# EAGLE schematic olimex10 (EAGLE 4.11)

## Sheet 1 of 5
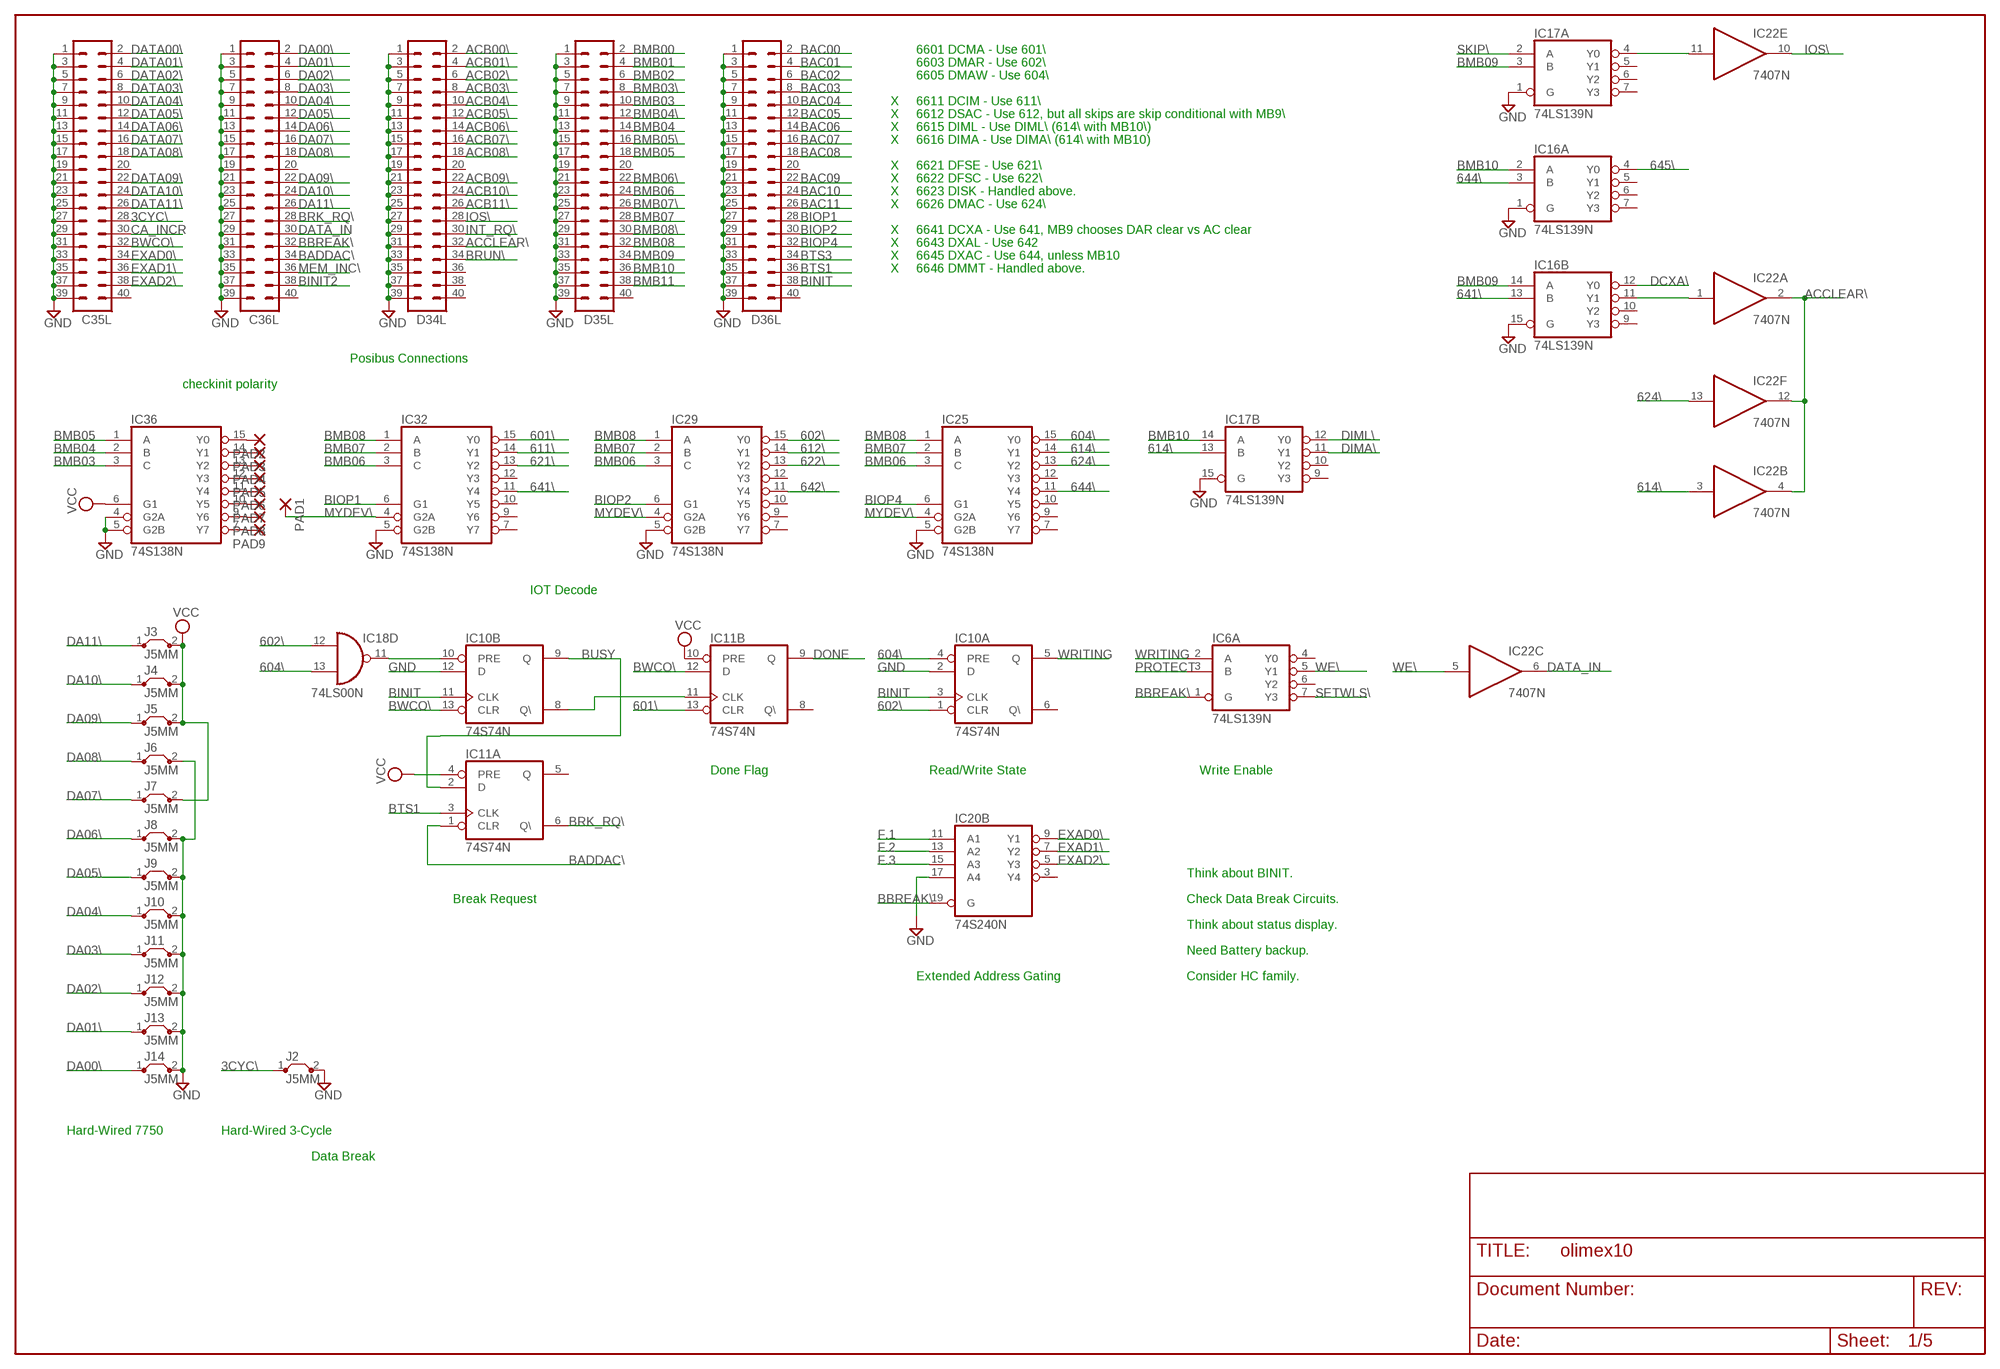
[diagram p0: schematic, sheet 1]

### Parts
C35L  MA20-2  [MA20-2]
C36L  MA20-2  [MA20-2]
D34L  MA20-2  [MA20-2]
D35L  MA20-2  [MA20-2]
D36L  MA20-2  [MA20-2]
IC6  74LS139N  74S139N  [DIL16]
IC10  74S74N  [DIL14]
IC11  74S74N  [DIL14]
IC16  74LS139N  74S139N  [DIL16]
IC17  74LS139N  74S139N  [DIL16]
IC18  74LS00N  [DIL14]
IC20  74S240N  [DIL20]
IC22  7407N  [DIL14]
IC25  74S138N  [DIL16]
IC29  74S138N  [DIL16]
IC32  74S138N  [DIL16]
IC36  74S138N  [DIL16]
J2  J5MM  [05]
J3  J5MM  [05]
J4  J5MM  [05]
J5  J5MM  [05]
J6  J5MM  [05]
J7  J5MM  [05]
J8  J5MM  [05]
J9  J5MM  [05]
J10  J5MM  [05]
J11  J5MM  [05]
J12  J5MM  [05]
J13  J5MM  [05]
J14  J5MM  [05]
PAD1  1,6/0,8  [1,6/0,8]
PAD2  1,6/0,8  [1,6/0,8]
PAD3  1,6/0,8  [1,6/0,8]
PAD4  1,6/0,8  [1,6/0,8]
PAD5  1,6/0,8  [1,6/0,8]
PAD6  1,6/0,8  [1,6/0,8]
PAD7  1,6/0,8  [1,6/0,8]
PAD8  1,6/0,8  [1,6/0,8]
PAD9  1,6/0,8  [1,6/0,8]

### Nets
3CYC\: C35L.28 J2.1
601\: IC11.13(B:CLR) IC32.15(Y0) ; also sheet 2
602\: IC10.1(A:CLR) IC18.12(D:I0) IC29.15(Y0) ; also sheet 2
604\: IC10.4(A:PRE) IC18.13(D:I1) IC25.15(Y0) ; also sheet 2
611\: IC32.14(Y1) ; also sheet 2
612\: IC29.14(Y1) ; also sheet 2
614\: IC17.13(B:B) IC22.3(B:I) IC25.14(Y1)
621\: IC32.13(Y2) ; also sheet 2
622\: IC29.13(Y2) ; also sheet 2
624\: IC22.13(F:I) IC25.13(Y2) ; also sheet 2
641\: IC16.13(B:B) IC32.11(Y4)
642\: IC29.11(Y4) ; also sheet 2
644\: IC16.3(A:B) IC25.11(Y4)
645\: IC16.4(A:Y0) ; also sheet 2
ACB00\: D34L.2 ; also sheet 2
ACB01\: D34L.4 ; also sheet 2
ACB02\: D34L.6 ; also sheet 2
ACB03\: D34L.8 ; also sheet 2
ACB04\: D34L.10 ; also sheet 2
ACB05\: D34L.12 ; also sheet 2
ACB06\: D34L.14 ; also sheet 2
ACB07\: D34L.16 ; also sheet 2
ACB08\: D34L.18 ; also sheet 2
ACB09\: D34L.22 ; also sheet 2
ACB10\: D34L.24 ; also sheet 2
ACB11\: D34L.26 ; also sheet 2
ACCLEAR\: D34L.32 IC22.2(A:O) IC22.4(B:O) IC22.12(F:O)
BAC00: D36L.2 ; also sheet 2
BAC01: D36L.4 ; also sheet 2
BAC02: D36L.6 ; also sheet 2
BAC03: D36L.8 ; also sheet 2
BAC04: D36L.10 ; also sheet 2
BAC05: D36L.12 ; also sheet 2
BAC06: D36L.14 ; also sheet 2
BAC07: D36L.16 ; also sheet 2
BAC08: D36L.18 ; also sheet 2
BAC09: D36L.22 ; also sheet 2
BAC10: D36L.24 ; also sheet 2
BAC11: D36L.26 ; also sheet 2
BADDAC\: C36L.34 IC11.1(A:CLR)
BBREAK\: C36L.32 IC6.1(A:G) IC20.19(B:G) ; also sheet 2,3
BINIT: D36L.38 IC10.3(A:CLK) IC10.11(B:CLK) ; also sheet 2
BINIT2: C36L.38
BIOP1: D36L.28 IC32.6(G1)
BIOP2: D36L.30 IC29.6(G1)
BIOP4: D36L.32 IC25.6(G1)
BMB00: D35L.2 ; also sheet 3
BMB01: D35L.4 ; also sheet 3
BMB02: D35L.6 ; also sheet 3
BMB03: D35L.10 IC36.3(C) ; also sheet 3
BMB03\: D35L.8
BMB04: D35L.14 IC36.2(B) ; also sheet 3
BMB04\: D35L.12
BMB05: D35L.18 IC36.1(A) ; also sheet 3
BMB05\: D35L.16
BMB06: D35L.24 IC25.3(C) IC29.3(C) IC32.3(C) ; also sheet 3
BMB06\: D35L.22
BMB07: D35L.28 IC25.2(B) IC29.2(B) IC32.2(B) ; also sheet 3
BMB07\: D35L.26
BMB08: D35L.32 IC25.1(A) IC29.1(A) IC32.1(A) ; also sheet 3
BMB08\: D35L.30
BMB09: D35L.34 IC16.14(B:A) IC17.3(A:B) ; also sheet 3
BMB10: D35L.36 IC16.2(A:A) IC17.14(B:A) ; also sheet 3
BMB11: D35L.38 ; also sheet 3
BRK_RQ\: C36L.28 IC11.6(A:Q\) ; also sheet 4,5
BRUN\: D34L.34
BTS1: D36L.36 IC11.3(A:CLK)
BTS3: D36L.34
BUSY: IC10.9(B:Q) IC11.2(A:D) ; also sheet 2
BWCO\: C35L.32 IC10.13(B:CLR) IC11.12(B:D) ; also sheet 4,5
CA_INCR: C35L.30
DA00\: C36L.2 J14.1
DA01\: C36L.4 J13.1
DA02\: C36L.6 J12.1
DA03\: C36L.8 J11.1
DA04\: C36L.10 J10.1
DA05\: C36L.12 J9.1
DA06\: C36L.14 J8.1
DA07\: C36L.16 J7.1
DA08\: C36L.18 J6.1
DA09\: C36L.22 J5.1
DA10\: C36L.24 J4.1
DA11\: C36L.26 J3.1
DATA00\: C35L.2 ; also sheet 3
DATA01\: C35L.4 ; also sheet 3
DATA02\: C35L.6 ; also sheet 3
DATA03\: C35L.8 ; also sheet 3
DATA04\: C35L.10 ; also sheet 3
DATA05\: C35L.12 ; also sheet 3
DATA06\: C35L.14 ; also sheet 3
DATA07\: C35L.16 ; also sheet 3
DATA08\: C35L.18 ; also sheet 3
DATA09\: C35L.22 ; also sheet 3
DATA10\: C35L.24 ; also sheet 3
DATA11\: C35L.26 ; also sheet 3
DATA_IN: C36L.30 IC22.6(C:O)
DCXA\: IC16.12(B:Y0) ; also sheet 2
DIMA\: IC17.11(B:Y1) ; also sheet 2
DIML\: IC17.12(B:Y0) ; also sheet 2
DONE: IC11.9(B:Q) ; also sheet 2,4,5
EXAD0\: C35L.34 IC20.9(B:Y1)
EXAD1\: C35L.36 IC20.7(B:Y2)
EXAD2\: C35L.38 IC20.5(B:Y3)
F.1: IC20.11(B:A1) ; also sheet 2,4,5
F.2: IC20.13(B:A2) ; also sheet 2,4,5
F.3: IC20.15(B:A3) ; also sheet 2,4,5
GND: C35L.1 C35L.3 C35L.5 C35L.7 C35L.9 C35L.11 C35L.13 C35L.15 C35L.17 C35L.19 C35L.21 C35L.23 C35L.25 C35L.27 C35L.29 C35L.31 C35L.33 C35L.35 C35L.37 C35L.39 C36L.1 C36L.3 C36L.5 C36L.7 C36L.9 C36L.11 C36L.13 C36L.15 C36L.17 C36L.19 C36L.21 C36L.23 C36L.25 C36L.27 C36L.29 C36L.31 C36L.33 C36L.35 C36L.37 C36L.39 D34L.1 D34L.3 D34L.5 D34L.7 D34L.9 D34L.11 D34L.13 D34L.15 D34L.17 D34L.19 D34L.21 D34L.23 D34L.25 D34L.27 D34L.29 D34L.31 D34L.33 D34L.35 D34L.37 D34L.39 D35L.1 D35L.3 D35L.5 D35L.7 D35L.9 D35L.11 D35L.13 D35L.15 D35L.17 D35L.19 D35L.21 D35L.23 D35L.25 D35L.27 D35L.29 D35L.31 D35L.33 D35L.35 D35L.37 D35L.39 D36L.1 D36L.3 D36L.5 D36L.7 D36L.9 D36L.11 D36L.13 D36L.15 D36L.17 D36L.19 D36L.21 D36L.23 D36L.25 D36L.27 D36L.29 D36L.31 D36L.33 D36L.35 D36L.37 D36L.39 IC10.2(A:D) IC10.12(B:D) IC16.1(A:G) IC16.15(B:G) IC17.1(A:G) IC17.15(B:G) IC20.17(B:A4) IC25.5(G2B) IC29.5(G2B) IC32.5(G2B) IC36.4(G2A) IC36.5(G2B) J2.2 J6.2 J8.2 J9.2 J10.2 J11.2 J12.2 J13.2 J14.2 ; also sheet 2,3,4,5
INT_RQ\: D34L.30 ; also sheet 2
IOS\: D34L.28 IC22.10(E:O)
MEM_INC\: C36L.36
MYDEV\: IC25.4(G2A) IC29.4(G2A) IC32.4(G2A) PAD1.1(P)
N$1: IC36.9(Y6) PAD8.1(P)
N$2: IC10.8(B:Q\) IC11.11(B:CLK)
N$5: IC36.15(Y0) PAD2.1(P)
N$6: IC36.14(Y1) PAD3.1(P)
N$7: IC36.13(Y2) PAD4.1(P)
N$8: IC36.12(Y3) PAD5.1(P)
N$9: IC36.11(Y4) PAD6.1(P)
N$10: IC36.10(Y5) PAD7.1(P)
N$11: IC36.7(Y7) PAD9.1(P)
N$26: IC16.11(B:Y1) IC22.1(A:I)
N$27: IC17.4(A:Y0) IC22.11(E:I)
N$31: IC10.10(B:PRE) IC18.11(D:O)
PROTECT: IC6.3(A:B) ; also sheet 3
SETWLS\: IC6.7(A:Y3) ; also sheet 2
SKIP\: IC17.2(A:A) ; also sheet 2
VCC [Power]: IC11.4(A:PRE) IC11.10(B:PRE) IC36.6(G1) J3.2 J4.2 J5.2 J7.2 ; also sheet 2,3,4,5
WE\: IC6.5(A:Y1) IC22.5(C:I) ; also sheet 3,4
WRITING: IC6.2(A:A) IC10.5(A:Q) ; also sheet 3,4,5
Unconnected: C35L.20 C35L.40 C36L.20 C36L.40 D34L.20 D34L.36 D34L.38 D34L.40 D35L.20 D35L.40 D36L.20 D36L.40 IC6.4(A:Y0) IC6.6(A:Y2) IC6.9(B:Y3) IC6.10(B:Y2) IC6.11(B:Y1) IC6.12(B:Y0) IC6.13(B:B) IC6.14(B:A) IC6.15(B:G) IC10.6(A:Q\) IC11.5(A:Q) IC11.8(B:Q\) IC16.5(A:Y1) IC16.6(A:Y2) IC16.7(A:Y3) IC16.9(B:Y3) IC16.10(B:Y2) IC17.5(A:Y1) IC17.6(A:Y2) IC17.7(A:Y3) IC17.9(B:Y3) IC17.10(B:Y2) IC20.1(A:G) IC20.2(A:A1) IC20.3(B:Y4) IC20.4(A:A2) IC20.6(A:A3) IC20.8(A:A4) IC20.12(A:Y4) IC20.14(A:Y3) IC20.16(A:Y2) IC20.18(A:Y1) IC22.8(D:O) IC22.9(D:I) IC25.7(Y7) IC25.9(Y6) IC25.10(Y5) IC25.12(Y3) IC29.7(Y7) IC29.9(Y6) IC29.10(Y5) IC29.12(Y3) IC32.7(Y7) IC32.9(Y6) IC32.10(Y5) IC32.12(Y3)

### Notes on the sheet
- 6601 DCMA - Use 601\
- 6603 DMAR - Use 602\
- 6605 DMAW - Use 604\
- X | 6611 DCIM - Use 611\
- X | 6612 DSAC - Use 612\, but all skips are skip conditional with MB9\
- X | 6615 DIML - Use DIML\ (614\ with MB10\)
- X | 6616 DIMA - Use DIMA\ (614\ with MB10)
- X | 6621 DFSE - Use 621\
- X | 6622 DFSC - Use 622\
- X | 6623 DISK - Handled above.
- X | 6626 DMAC - Use 624\
- X | 6641 DCXA - Use 641, MB9 chooses DAR clear vs AC clear
- X | 6643 DXAL - Use 642
- X | 6645 DXAC - Use 644, unless MB10
- X | 6646 DMMT - Handled above.
- Posibus Connections
- checkinit polarity
- IOT Decode
- Done Flag | Read/Write State | Write Enable
- Think about BINIT.
- Break Request | Check Data Break Circuits.
- Think about status display.
- Need Battery backup.
- Extended Address Gating | Consider HC family.
- Hard-Wired 7750 | Hard-Wired 3-Cycle
- Data Break

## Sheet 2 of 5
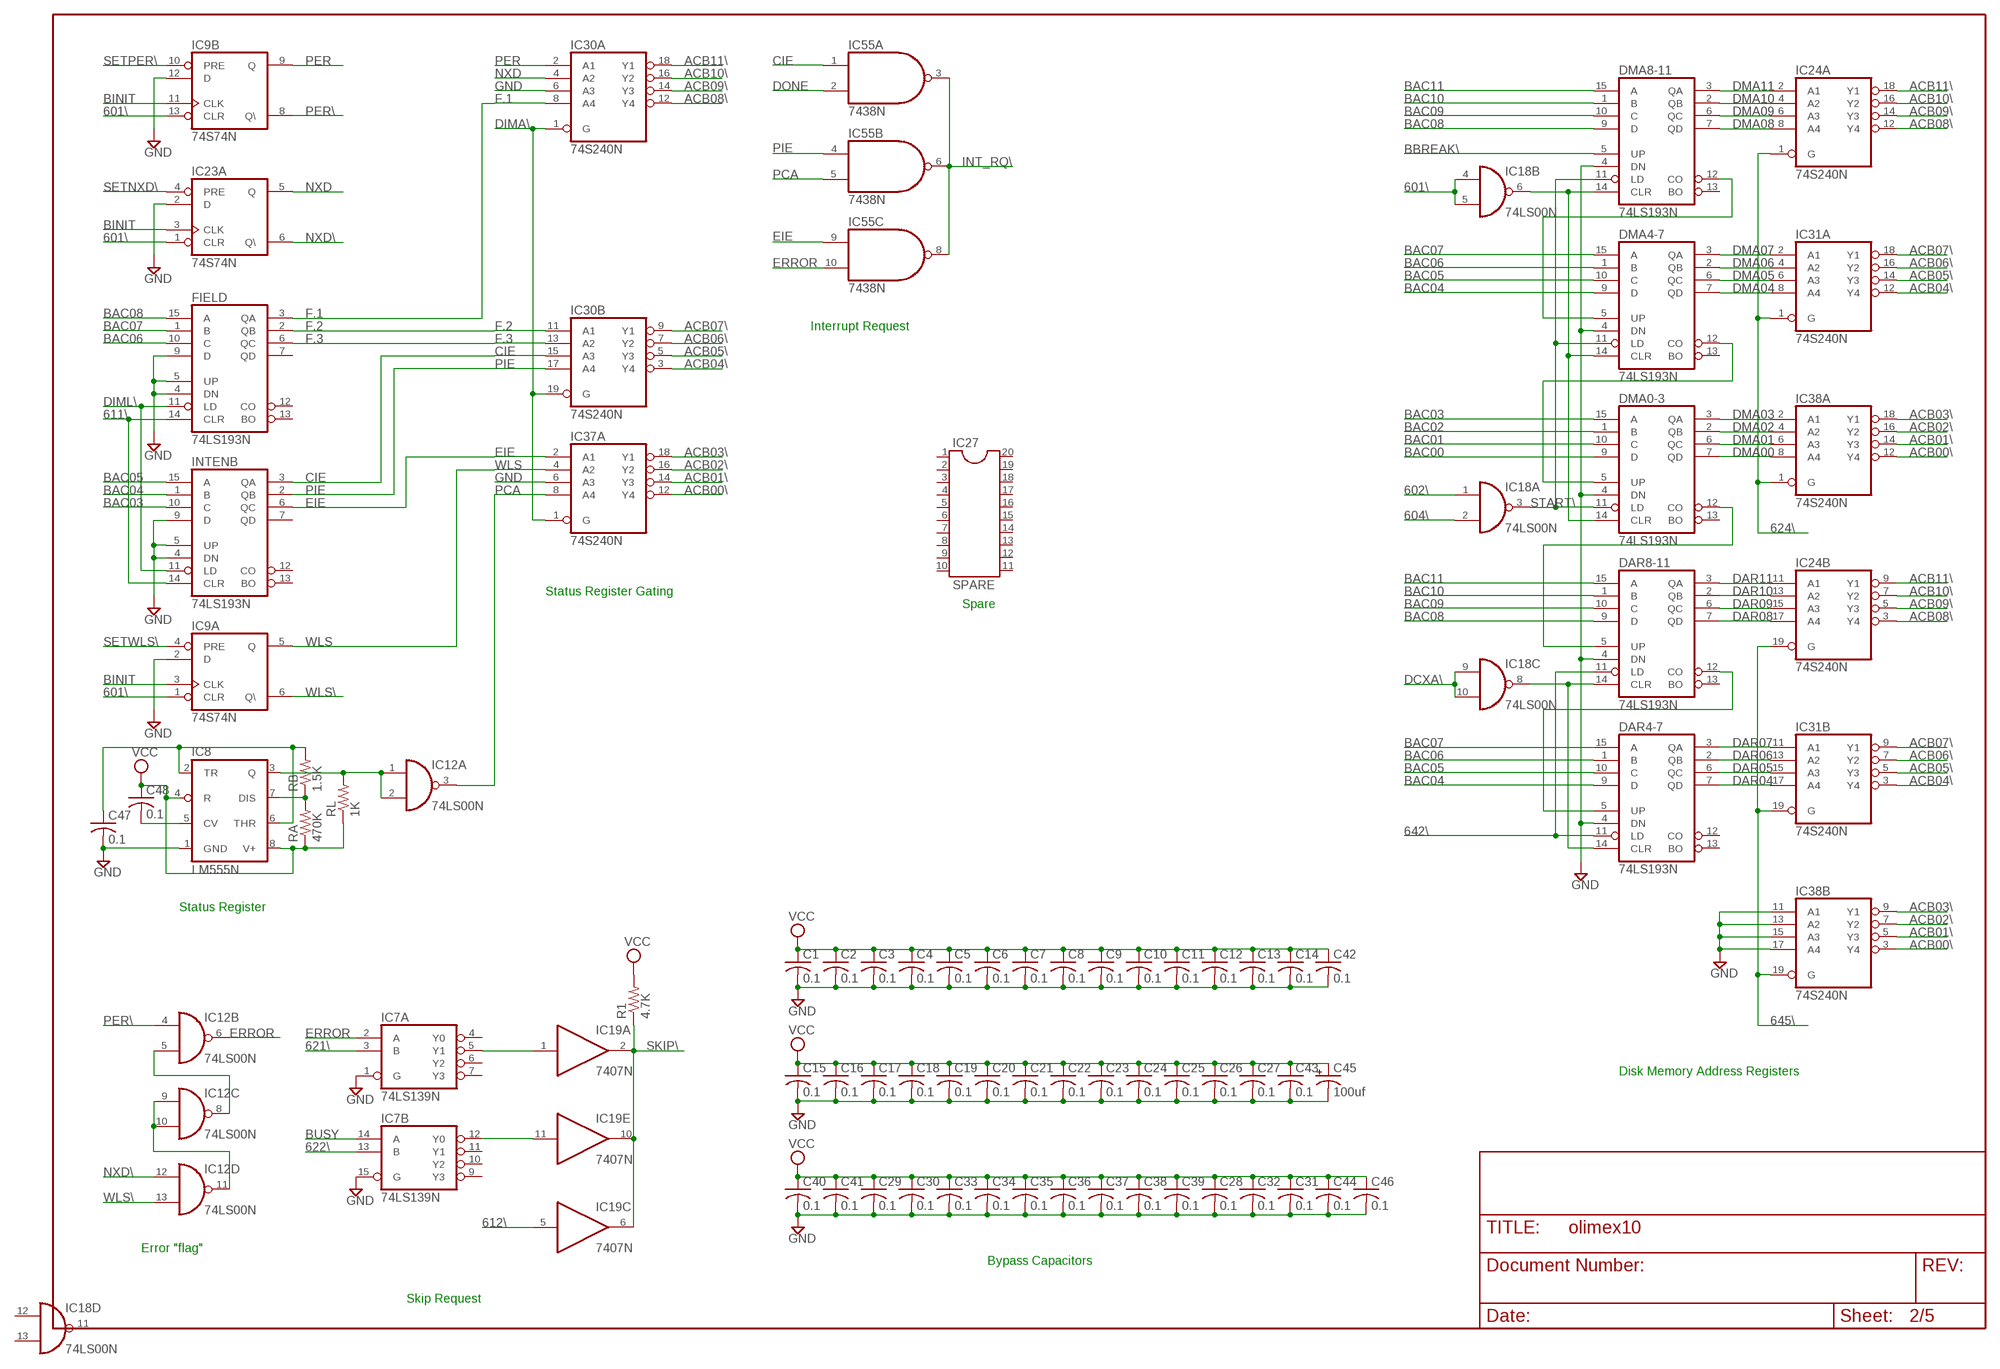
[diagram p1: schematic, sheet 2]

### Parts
C1  0.1  C-US050-025X075  [C050-025X075]
C2  0.1  C-US050-025X075  [C050-025X075]
C3  0.1  C-US050-025X075  [C050-025X075]
C4  0.1  C-US050-025X075  [C050-025X075]
C5  0.1  C-US050-025X075  [C050-025X075]
C6  0.1  C-US050-025X075  [C050-025X075]
C7  0.1  C-US050-025X075  [C050-025X075]
C8  0.1  C-US050-025X075  [C050-025X075]
C9  0.1  C-US050-025X075  [C050-025X075]
C10  0.1  C-US050-025X075  [C050-025X075]
C11  0.1  C-US050-025X075  [C050-025X075]
C12  0.1  C-US050-025X075  [C050-025X075]
C13  0.1  C-US050-025X075  [C050-025X075]
C14  0.1  C-US050-025X075  [C050-025X075]
C15  0.1  C-US050-025X075  [C050-025X075]
C16  0.1  C-US050-025X075  [C050-025X075]
C17  0.1  C-US050-025X075  [C050-025X075]
C18  0.1  C-US050-025X075  [C050-025X075]
C19  0.1  C-US050-025X075  [C050-025X075]
C20  0.1  C-US050-025X075  [C050-025X075]
C21  0.1  C-US050-025X075  [C050-025X075]
C22  0.1  C-US050-025X075  [C050-025X075]
C23  0.1  C-US050-025X075  [C050-025X075]
C24  0.1  C-US050-025X075  [C050-025X075]
C25  0.1  C-US050-025X075  [C050-025X075]
C26  0.1  C-US050-025X075  [C050-025X075]
C27  0.1  C-US050-025X075  [C050-025X075]
C28  0.1  C-US050-025X075  [C050-025X075]
C29  0.1  C-US050-025X075  [C050-025X075]
C30  0.1  C-US050-025X075  [C050-025X075]
C31  0.1  C-US050-025X075  [C050-025X075]
C32  0.1  C-US050-025X075  [C050-025X075]
C33  0.1  C-US050-025X075  [C050-025X075]
C34  0.1  C-US050-025X075  [C050-025X075]
C35  0.1  C-US050-025X075  [C050-025X075]
C36  0.1  C-US050-025X075  [C050-025X075]
C37  0.1  C-US050-025X075  [C050-025X075]
C38  0.1  C-US050-025X075  [C050-025X075]
C39  0.1  C-US050-025X075  [C050-025X075]
C40  0.1  C-US050-025X075  [C050-025X075]
C41  0.1  C-US050-025X075  [C050-025X075]
C42  0.1  C-US050-025X075  [C050-025X075]
C43  0.1  C-US050-025X075  [C050-025X075]
C44  0.1  C-US050-025X075  [C050-025X075]
C45  100uf  CPOL-USE22-6AXIAL  [E22-6]
C46  0.1  C-US050-025X075  [C050-025X075]
C47  0.1  C-US050-025X075  [C050-025X075]
C48  0.1  C-US050-025X075  [C050-025X075]
DAR4-7  74LS193N  74LS192N  [DIL16]
DAR8-11  74LS193N  74LS192N  [DIL16]
DMA0-3  74LS193N  74LS192N  [DIL16]
DMA4-7  74LS193N  74LS192N  [DIL16]
DMA8-11  74LS193N  74LS192N  [DIL16]
FIELD  74LS193N  74LS192N  [DIL16]
IC7  74LS139N  [DIL16]
IC8  LM555N  [DIL08]
IC9  74S74N  [DIL14]
IC12  74LS00N  [DIL14]
IC19  7407N  [DIL14]
IC23  74S74N  [DIL14]
IC24  74S240N  [DIL20]
IC27  SPARE  DIL20  [DIL20]
IC30  74S240N  [DIL20]
IC31  74S240N  [DIL20]
IC37  74S240N  [DIL20]
IC38  74S240N  [DIL20]
IC55  7438N  [DIL14]
INTENB  74LS193N  74LS192N  [DIL16]
R1  4.7K  R-US_0207/10  [0207/10]
RA  470K  R-US_0207/10  [0207/10]
RB  1.5K  R-US_0207/10  [0207/10]
RL  1K  R-US_0207/10  [0207/10]

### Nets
601\: IC9.1(A:CLR) IC9.13(B:CLR) IC18.4(B:I0) IC18.5(B:I1) IC23.1(A:CLR) ; also sheet 1
602\: IC18.1(A:I0) ; also sheet 1
604\: IC18.2(A:I1) ; also sheet 1
611\: FIELD.14(CLR) INTENB.14(CLR) ; also sheet 1
612\: IC19.5(C:I) ; also sheet 1
621\: IC7.3(A:B) ; also sheet 1
622\: IC7.13(B:B) ; also sheet 1
624\: IC24.1(A:G) IC31.1(A:G) IC38.1(A:G) ; also sheet 1
642\: DAR4-7.11(LD) DAR8-11.11(LD) ; also sheet 1
645\: IC24.19(B:G) IC31.19(B:G) IC38.19(B:G) ; also sheet 1
ACB00\: IC37.12(A:Y4) IC38.3(B:Y4) IC38.12(A:Y4) ; also sheet 1
ACB01\: IC37.14(A:Y3) IC38.5(B:Y3) IC38.14(A:Y3) ; also sheet 1
ACB02\: IC37.16(A:Y2) IC38.7(B:Y2) IC38.16(A:Y2) ; also sheet 1
ACB03\: IC37.18(A:Y1) IC38.9(B:Y1) IC38.18(A:Y1) ; also sheet 1
ACB04\: IC30.3(B:Y4) IC31.3(B:Y4) IC31.12(A:Y4) ; also sheet 1
ACB05\: IC30.5(B:Y3) IC31.5(B:Y3) IC31.14(A:Y3) ; also sheet 1
ACB06\: IC30.7(B:Y2) IC31.7(B:Y2) IC31.16(A:Y2) ; also sheet 1
ACB07\: IC30.9(B:Y1) IC31.9(B:Y1) IC31.18(A:Y1) ; also sheet 1
ACB08\: IC24.3(B:Y4) IC24.12(A:Y4) IC30.12(A:Y4) ; also sheet 1
ACB09\: IC24.5(B:Y3) IC24.14(A:Y3) IC30.14(A:Y3) ; also sheet 1
ACB10\: IC24.7(B:Y2) IC24.16(A:Y2) IC30.16(A:Y2) ; also sheet 1
ACB11\: IC24.9(B:Y1) IC24.18(A:Y1) IC30.18(A:Y1) ; also sheet 1
BAC00: DMA0-3.9(D) ; also sheet 1
BAC01: DMA0-3.10(C) ; also sheet 1
BAC02: DMA0-3.1(B) ; also sheet 1
BAC03: DMA0-3.15(A) INTENB.10(C) ; also sheet 1
BAC04: DAR4-7.9(D) DMA4-7.9(D) INTENB.1(B) ; also sheet 1
BAC05: DAR4-7.10(C) DMA4-7.10(C) INTENB.15(A) ; also sheet 1
BAC06: DAR4-7.1(B) DMA4-7.1(B) FIELD.10(C) ; also sheet 1
BAC07: DAR4-7.15(A) DMA4-7.15(A) FIELD.1(B) ; also sheet 1
BAC08: DAR8-11.9(D) DMA8-11.9(D) FIELD.15(A) ; also sheet 1
BAC09: DAR8-11.10(C) DMA8-11.10(C) ; also sheet 1
BAC10: DAR8-11.1(B) DMA8-11.1(B) ; also sheet 1
BAC11: DAR8-11.15(A) DMA8-11.15(A) ; also sheet 1
BBREAK\: DMA8-11.5(UP) ; also sheet 1,3
BINIT: IC9.3(A:CLK) IC9.11(B:CLK) IC23.3(A:CLK) ; also sheet 1
BUSY: IC7.14(B:A) ; also sheet 1
CIE: IC30.15(B:A3) IC55.1(A:I0) INTENB.3(QA) ; also sheet 4,5
DAR04: DAR4-7.7(QD) IC31.17(B:A4) ; also sheet 3,4,5
DAR05: DAR4-7.6(QC) IC31.15(B:A3) ; also sheet 3,4,5
DAR06: DAR4-7.2(QB) IC31.13(B:A2) ; also sheet 3,4,5
DAR07: DAR4-7.3(QA) IC31.11(B:A1) ; also sheet 3,4,5
DAR08: DAR8-11.7(QD) IC24.17(B:A4) ; also sheet 3,4,5
DAR09: DAR8-11.6(QC) IC24.15(B:A3) ; also sheet 3,4,5
DAR10: DAR8-11.2(QB) IC24.13(B:A2) ; also sheet 3,4,5
DAR11: DAR8-11.3(QA) IC24.11(B:A1) ; also sheet 3,4,5
DCXA\: IC18.9(C:I0) IC18.10(C:I1) ; also sheet 1
DIMA\: IC30.1(A:G) IC30.19(B:G) IC37.1(A:G) ; also sheet 1
DIML\: FIELD.11(LD) INTENB.11(LD) ; also sheet 1
DMA00: DMA0-3.7(QD) IC38.8(A:A4) ; also sheet 3,4,5
DMA01: DMA0-3.6(QC) IC38.6(A:A3) ; also sheet 3,4,5
DMA02: DMA0-3.2(QB) IC38.4(A:A2) ; also sheet 3,4,5
DMA03: DMA0-3.3(QA) IC38.2(A:A1) ; also sheet 3,4,5
DMA04: DMA4-7.7(QD) IC31.8(A:A4) ; also sheet 3,4,5
DMA05: DMA4-7.6(QC) IC31.6(A:A3) ; also sheet 3,4,5
DMA06: DMA4-7.2(QB) IC31.4(A:A2) ; also sheet 3,4,5
DMA07: DMA4-7.3(QA) IC31.2(A:A1) ; also sheet 3,4,5
DMA08: DMA8-11.7(QD) IC24.8(A:A4) ; also sheet 3,4,5
DMA09: DMA8-11.6(QC) IC24.6(A:A3) ; also sheet 3,4,5
DMA10: DMA8-11.2(QB) IC24.4(A:A2) ; also sheet 3,4,5
DMA11: DMA8-11.3(QA) IC24.2(A:A1) ; also sheet 3,4,5
DONE: IC55.2(A:I1) ; also sheet 1,4,5
EIE: IC37.2(A:A1) IC55.9(C:I0) INTENB.6(QC) ; also sheet 4,5
ERROR: IC7.2(A:A) IC12.6(B:O) IC55.10(C:I1)
F.1: FIELD.3(QA) IC30.8(A:A4) ; also sheet 1,4,5
F.2: FIELD.2(QB) IC30.11(B:A1) ; also sheet 1,4,5
F.3: FIELD.6(QC) IC30.13(B:A2) ; also sheet 1,4,5
GND: C1.2 C2.2 C3.2 C4.2 C5.2 C6.2 C7.2 C8.2 C9.2 C10.2 C11.2 C12.2 C13.2 C14.2 C15.2 C16.2 C17.2 C18.2 C19.2 C20.2 C21.2 C22.2 C23.2 C24.2 C25.2 C26.2 C27.2 C28.2 C29.2 C30.2 C31.2 C32.2 C33.2 C34.2 C35.2 C36.2 C37.2 C38.2 C39.2 C40.2 C41.2 C42.2 C43.2 C44.2 C45.- C46.2 C47.2 DAR4-7.4(DN) DAR8-11.4(DN) DMA0-3.4(DN) DMA4-7.4(DN) DMA8-11.4(DN) FIELD.4(DN) FIELD.5(UP) FIELD.9(D) IC7.1(A:G) IC7.15(B:G) IC8.1(GND) IC9.2(A:D) IC9.12(B:D) IC23.2(A:D) IC30.6(A:A3) IC37.6(A:A3) IC38.11(B:A1) IC38.13(B:A2) IC38.15(B:A3) IC38.17(B:A4) INTENB.4(DN) INTENB.5(UP) INTENB.9(D) ; also sheet 1,3,4,5
INT_RQ\: IC55.3(A:O) IC55.6(B:O) IC55.8(C:O) ; also sheet 1
N$3: DMA0-3.5(UP) DMA4-7.12(CO)
N$12: DAR4-7.14(CLR) DAR8-11.14(CLR) IC18.8(C:O)
N$13: DMA4-7.5(UP) DMA8-11.12(CO)
N$16: DAR8-11.5(UP) DMA0-3.12(CO)
N$22: DMA0-3.14(CLR) DMA4-7.14(CLR) DMA8-11.14(CLR) IC18.6(B:O)
N$25: DAR4-7.5(UP) DAR8-11.12(CO)
N$28: IC7.5(A:Y1) IC19.1(A:I)
N$29: IC8.7(DIS) RA.2 RB.1
N$30: IC8.3(Q) IC12.1(A:I0) IC12.2(A:I1) RL.2
N$32: C47.1 IC8.2(TR) IC8.6(THR) RB.2
N$33: IC7.12(B:Y0) IC19.11(E:I)
N$34: C48.2 IC8.5(CV)
N$37: IC12.9(C:I0) IC12.10(C:I1) IC12.11(D:O)
N$40: IC12.5(B:I1) IC12.8(C:O)
NXD: IC23.5(A:Q) IC30.4(A:A2) ; also sheet 4,5
NXD\: IC12.12(D:I0) IC23.6(A:Q\)
PCA: IC12.3(A:O) IC37.8(A:A4) IC55.5(B:I1)
PER: IC9.9(B:Q) IC30.2(A:A1) ; also sheet 4,5
PER\: IC9.8(B:Q\) IC12.4(B:I0)
PIE: IC30.17(B:A4) IC55.4(B:I0) INTENB.2(QB) ; also sheet 4,5
SETNXD\: IC23.4(A:PRE) ; also sheet 3
SETPER\: IC9.10(B:PRE) ; also sheet 3
SETWLS\: IC9.4(A:PRE) ; also sheet 1
SKIP\: IC19.2(A:O) IC19.6(C:O) IC19.10(E:O) R1.1 ; also sheet 1
START\: DMA0-3.11(LD) DMA4-7.11(LD) DMA8-11.11(LD) IC18.3(A:O)
VCC [Power]: C1.1 C2.1 C3.1 C4.1 C5.1 C6.1 C7.1 C8.1 C9.1 C10.1 C11.1 C12.1 C13.1 C14.1 C15.1 C16.1 C17.1 C18.1 C19.1 C20.1 C21.1 C22.1 C23.1 C24.1 C25.1 C26.1 C27.1 C28.1 C29.1 C30.1 C31.1 C32.1 C33.1 C34.1 C35.1 C36.1 C37.1 C38.1 C39.1 C40.1 C41.1 C42.1 C43.1 C44.1 C45.+ C46.1 C48.1 IC8.4(R) IC8.8(V+) R1.2 RA.1 RL.1 ; also sheet 1,3,4,5
WLS: IC9.5(A:Q) IC37.4(A:A2) ; also sheet 4,5
WLS\: IC9.6(A:Q\) IC12.13(D:I1)
Unconnected: DAR4-7.12(CO) DAR4-7.13(BO) DAR8-11.13(BO) DMA0-3.13(BO) DMA4-7.13(BO) DMA8-11.13(BO) FIELD.7(QD) FIELD.12(CO) FIELD.13(BO) IC7.4(A:Y0) IC7.6(A:Y2) IC7.7(A:Y3) IC7.9(B:Y3) IC7.10(B:Y2) IC7.11(B:Y1) IC19.3(B:I) IC19.4(B:O) IC19.8(D:O) IC19.9(D:I) IC19.12(F:O) IC19.13(F:I) IC23.8(B:Q\) IC23.9(B:Q) IC23.10(B:PRE) IC23.11(B:CLK) IC23.12(B:D) IC23.13(B:CLR) IC27.1 IC27.2 IC27.3 IC27.4 IC27.5 IC27.6 IC27.7 IC27.8 IC27.9 IC27.10 IC27.11 IC27.12 IC27.13 IC27.14 IC27.15 IC27.16 IC27.17 IC27.18 IC27.19 IC27.20 IC37.3(B:Y4) IC37.5(B:Y3) IC37.7(B:Y2) IC37.9(B:Y1) IC37.11(B:A1) IC37.13(B:A2) IC37.15(B:A3) IC37.17(B:A4) IC37.19(B:G) IC55.11(D:O) IC55.12(D:I0) IC55.13(D:I1) INTENB.7(QD) INTENB.12(CO) INTENB.13(BO)

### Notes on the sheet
- Interrupt Request
- Status Register Gating
- Spare
- Status Register
- Disk Memory Address Registers
- Error "flag"
- Bypass Capacitors
- Skip Request

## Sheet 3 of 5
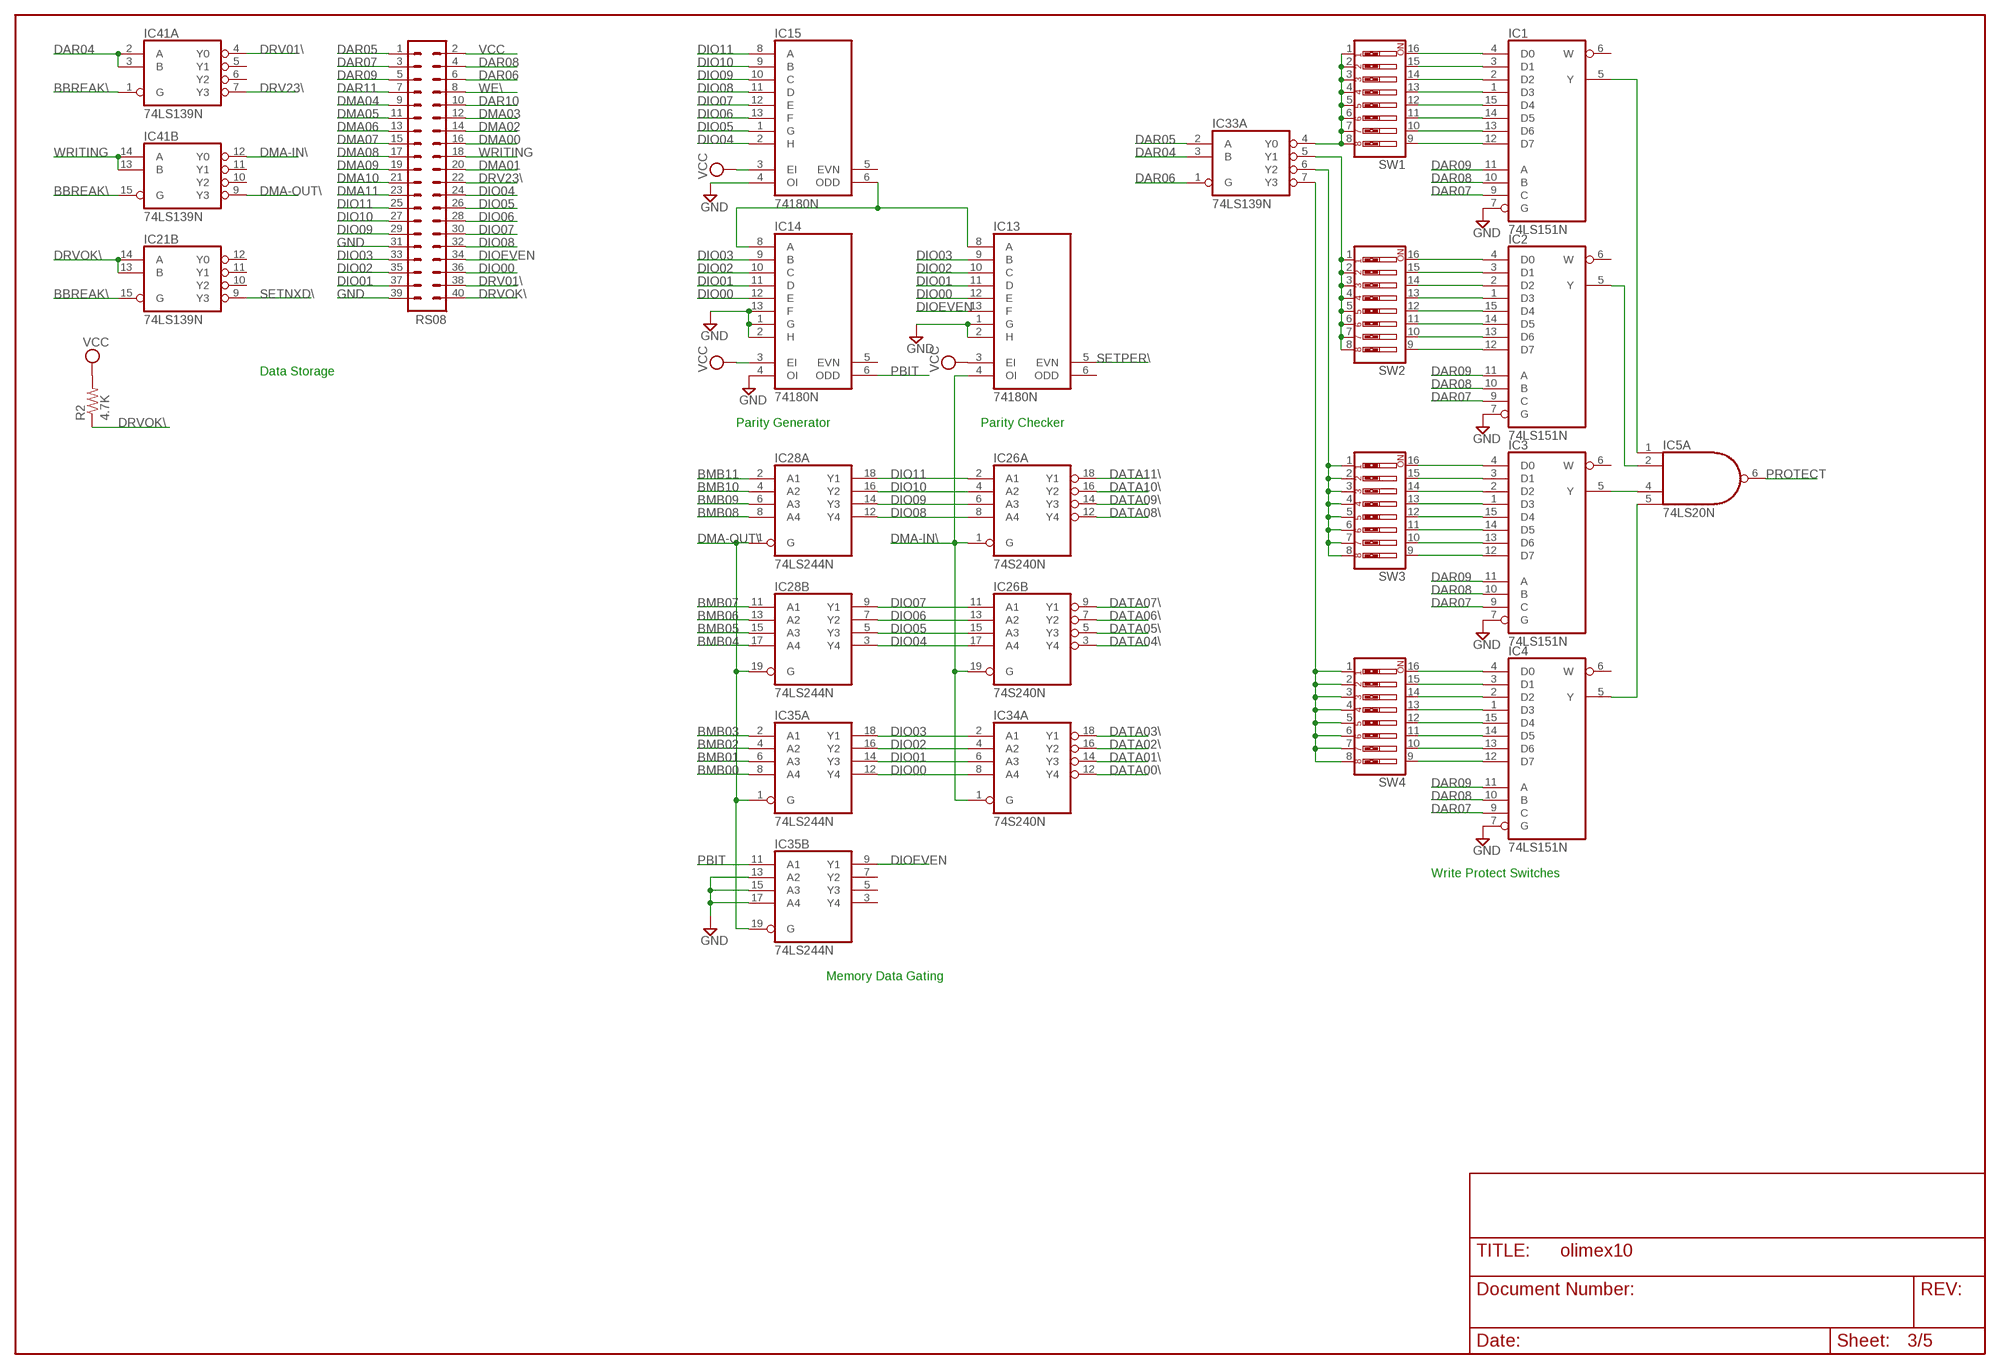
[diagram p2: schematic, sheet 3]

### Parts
IC1  74LS151N  [DIL16]
IC2  74LS151N  [DIL16]
IC3  74LS151N  [DIL16]
IC4  74LS151N  [DIL16]
IC5  74LS20N  [DIL14]
IC13  74180N  [DIL14]
IC14  74180N  [DIL14]
IC15  74180N  [DIL14]
IC21  74LS139N  [DIL16]
IC26  74S240N  [DIL20]
IC28  74LS244N  [DIL20]
IC33  74LS139N  [DIL16]
IC34  74S240N  [DIL20]
IC35  74LS244N  [DIL20]
IC41  74LS139N  [DIL16]
R2  4.7K  R-US_0207/10  [0207/10]
RS08  MA20-2  [MA20-2]
SW1  SW_DIP-8  [EDG-08]
SW2  SW_DIP-8  [EDG-08]
SW3  SW_DIP-8  [EDG-08]
SW4  SW_DIP-8  [EDG-08]

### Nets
BBREAK\: IC21.15(B:G) IC41.1(A:G) IC41.15(B:G) ; also sheet 1,2
BMB00: IC35.8(A:A4) ; also sheet 1
BMB01: IC35.6(A:A3) ; also sheet 1
BMB02: IC35.4(A:A2) ; also sheet 1
BMB03: IC35.2(A:A1) ; also sheet 1
BMB04: IC28.17(B:A4) ; also sheet 1
BMB05: IC28.15(B:A3) ; also sheet 1
BMB06: IC28.13(B:A2) ; also sheet 1
BMB07: IC28.11(B:A1) ; also sheet 1
BMB08: IC28.8(A:A4) ; also sheet 1
BMB09: IC28.6(A:A3) ; also sheet 1
BMB10: IC28.4(A:A2) ; also sheet 1
BMB11: IC28.2(A:A1) ; also sheet 1
DAR04: IC33.3(A:B) IC41.2(A:A) IC41.3(A:B) ; also sheet 2,4,5
DAR05: IC33.2(A:A) RS08.1 ; also sheet 2,4,5
DAR06: IC33.1(A:G) RS08.6 ; also sheet 2,4,5
DAR07: IC1.9(C) IC2.9(C) IC3.9(C) IC4.9(C) RS08.3 ; also sheet 2,4,5
DAR08: IC1.10(B) IC2.10(B) IC3.10(B) IC4.10(B) RS08.4 ; also sheet 2,4,5
DAR09: IC1.11(A) IC2.11(A) IC3.11(A) IC4.11(A) RS08.5 ; also sheet 2,4,5
DAR10: RS08.10 ; also sheet 2,4,5
DAR11: RS08.7 ; also sheet 2,4,5
DATA00\: IC34.12(A:Y4) ; also sheet 1
DATA01\: IC34.14(A:Y3) ; also sheet 1
DATA02\: IC34.16(A:Y2) ; also sheet 1
DATA03\: IC34.18(A:Y1) ; also sheet 1
DATA04\: IC26.3(B:Y4) ; also sheet 1
DATA05\: IC26.5(B:Y3) ; also sheet 1
DATA06\: IC26.7(B:Y2) ; also sheet 1
DATA07\: IC26.9(B:Y1) ; also sheet 1
DATA08\: IC26.12(A:Y4) ; also sheet 1
DATA09\: IC26.14(A:Y3) ; also sheet 1
DATA10\: IC26.16(A:Y2) ; also sheet 1
DATA11\: IC26.18(A:Y1) ; also sheet 1
DIO00: IC13.12(E) IC14.12(E) IC34.8(A:A4) IC35.12(A:Y4) RS08.36 ; also sheet 4,5
DIO01: IC13.11(D) IC14.11(D) IC34.6(A:A3) IC35.14(A:Y3) RS08.37 ; also sheet 4,5
DIO02: IC13.10(C) IC14.10(C) IC34.4(A:A2) IC35.16(A:Y2) RS08.35 ; also sheet 4,5
DIO03: IC13.9(B) IC14.9(B) IC34.2(A:A1) IC35.18(A:Y1) RS08.33 ; also sheet 4,5
DIO04: IC15.2(H) IC26.17(B:A4) IC28.3(B:Y4) RS08.24 ; also sheet 4,5
DIO05: IC15.1(G) IC26.15(B:A3) IC28.5(B:Y3) RS08.26 ; also sheet 4,5
DIO06: IC15.13(F) IC26.13(B:A2) IC28.7(B:Y2) RS08.28 ; also sheet 4,5
DIO07: IC15.12(E) IC26.11(B:A1) IC28.9(B:Y1) RS08.30 ; also sheet 4,5
DIO08: IC15.11(D) IC26.8(A:A4) IC28.12(A:Y4) RS08.32 ; also sheet 4,5
DIO09: IC15.10(C) IC26.6(A:A3) IC28.14(A:Y3) RS08.29 ; also sheet 4,5
DIO10: IC15.9(B) IC26.4(A:A2) IC28.16(A:Y2) RS08.27 ; also sheet 4,5
DIO11: IC15.8(A) IC26.2(A:A1) IC28.18(A:Y1) RS08.25 ; also sheet 4,5
DIOEVEN: IC13.13(F) IC35.9(B:Y1) RS08.34 ; also sheet 4
DMA00: RS08.16 ; also sheet 2,4,5
DMA01: RS08.20 ; also sheet 2,4,5
DMA02: RS08.14 ; also sheet 2,4,5
DMA03: RS08.12 ; also sheet 2,4,5
DMA04: RS08.9 ; also sheet 2,4,5
DMA05: RS08.11 ; also sheet 2,4,5
DMA06: RS08.13 ; also sheet 2,4,5
DMA07: RS08.15 ; also sheet 2,4,5
DMA08: RS08.17 ; also sheet 2,4,5
DMA09: RS08.19 ; also sheet 2,4,5
DMA10: RS08.21 ; also sheet 2,4,5
DMA11: RS08.23 ; also sheet 2,4,5
DMA-IN\: IC13.4(OI) IC26.1(A:G) IC26.19(B:G) IC34.1(A:G) IC41.12(B:Y0)
DMA-OUT\: IC28.1(A:G) IC28.19(B:G) IC35.1(A:G) IC35.19(B:G) IC41.9(B:Y3)
DRV01\: IC41.4(A:Y0) RS08.38 ; also sheet 4
DRV23\: IC41.7(A:Y3) RS08.22 ; also sheet 4
DRVOK\: IC21.13(B:B) IC21.14(B:A) R2.1 RS08.40 ; also sheet 4
GND: IC1.7(G) IC2.7(G) IC3.7(G) IC4.7(G) IC13.1(G) IC13.2(H) IC14.1(G) IC14.2(H) IC14.4(OI) IC14.13(F) IC15.4(OI) IC35.13(B:A2) IC35.15(B:A3) IC35.17(B:A4) RS08.31 RS08.39 ; also sheet 1,2,4,5
N$4: IC33.4(A:Y0) SW1.1 SW1.2 SW1.3 SW1.4 SW1.5 SW1.6 SW1.7 SW1.8
N$14: IC13.8(A) IC14.8(A) IC15.6(ODD)
N$15: IC2.5(Y) IC5.2(A:I1)
N$17: IC33.5(A:Y1) SW2.1 SW2.2 SW2.3 SW2.4 SW2.5 SW2.6 SW2.7 SW2.8
N$19: IC33.6(A:Y2) SW3.1 SW3.2 SW3.3 SW3.4 SW3.5 SW3.6 SW3.7 SW3.8
N$20: IC33.7(A:Y3) SW4.1 SW4.2 SW4.3 SW4.4 SW4.5 SW4.6 SW4.7 SW4.8
N$21: IC3.5(Y) IC5.4(A:I2)
N$23: IC1.5(Y) IC5.1(A:I0)
N$24: IC4.5(Y) IC5.5(A:I3)
N$53: IC1.4(D0) SW1.16
N$54: IC1.3(D1) SW1.15
N$55: IC1.2(D2) SW1.14
N$56: IC1.1(D3) SW1.13
N$57: IC1.14(D5) SW1.11
N$58: IC1.13(D6) SW1.10
N$59: IC1.12(D7) SW1.9
N$60: IC1.15(D4) SW1.12
N$61: IC2.4(D0) SW2.16
N$62: IC2.3(D1) SW2.15
N$63: IC2.2(D2) SW2.14
N$64: IC2.1(D3) SW2.13
N$65: IC2.14(D5) SW2.11
N$66: IC2.13(D6) SW2.10
N$67: IC2.12(D7) SW2.9
N$68: IC3.4(D0) SW3.16
N$69: IC3.3(D1) SW3.15
N$70: IC3.2(D2) SW3.14
N$71: IC3.1(D3) SW3.13
N$72: IC3.14(D5) SW3.11
N$73: IC3.13(D6) SW3.10
N$74: IC3.12(D7) SW3.9
N$75: IC4.4(D0) SW4.16
N$76: IC4.3(D1) SW4.15
N$77: IC4.2(D2) SW4.14
N$78: IC4.1(D3) SW4.13
N$79: IC4.14(D5) SW4.11
N$80: IC4.13(D6) SW4.10
N$81: IC4.12(D7) SW4.9
N$82: IC4.15(D4) SW4.12
N$83: IC3.15(D4) SW3.12
N$84: IC2.15(D4) SW2.12
PBIT: IC14.6(ODD) IC35.11(B:A1)
PROTECT: IC5.6(A:O) ; also sheet 1
SETNXD\: IC21.9(B:Y3) ; also sheet 2
SETPER\: IC13.5(EVN) ; also sheet 2
VCC [Power]: IC13.3(EI) IC14.3(EI) IC15.3(EI) R2.2 RS08.2 ; also sheet 1,2,4,5
WE\: RS08.8 ; also sheet 1,4
WRITING: IC41.13(B:B) IC41.14(B:A) RS08.18 ; also sheet 1,4,5
Unconnected: IC1.6(W) IC2.6(W) IC3.6(W) IC4.6(W) IC5.8(B:O) IC5.9(B:I0) IC5.10(B:I1) IC5.12(B:I2) IC5.13(B:I3) IC13.6(ODD) IC14.5(EVN) IC15.5(EVN) IC21.1(A:G) IC21.2(A:A) IC21.3(A:B) IC21.4(A:Y0) IC21.5(A:Y1) IC21.6(A:Y2) IC21.7(A:Y3) IC21.10(B:Y2) IC21.11(B:Y1) IC21.12(B:Y0) IC33.9(B:Y3) IC33.10(B:Y2) IC33.11(B:Y1) IC33.12(B:Y0) IC33.13(B:B) IC33.14(B:A) IC33.15(B:G) IC34.3(B:Y4) IC34.5(B:Y3) IC34.7(B:Y2) IC34.9(B:Y1) IC34.11(B:A1) IC34.13(B:A2) IC34.15(B:A3) IC34.17(B:A4) IC34.19(B:G) IC35.3(B:Y4) IC35.5(B:Y3) IC35.7(B:Y2) IC41.5(A:Y1) IC41.6(A:Y2) IC41.10(B:Y2) IC41.11(B:Y1)

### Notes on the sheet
- Data Storage
- Parity Generator | Parity Checker
- Write Protect Switches
- Memory Data Gating

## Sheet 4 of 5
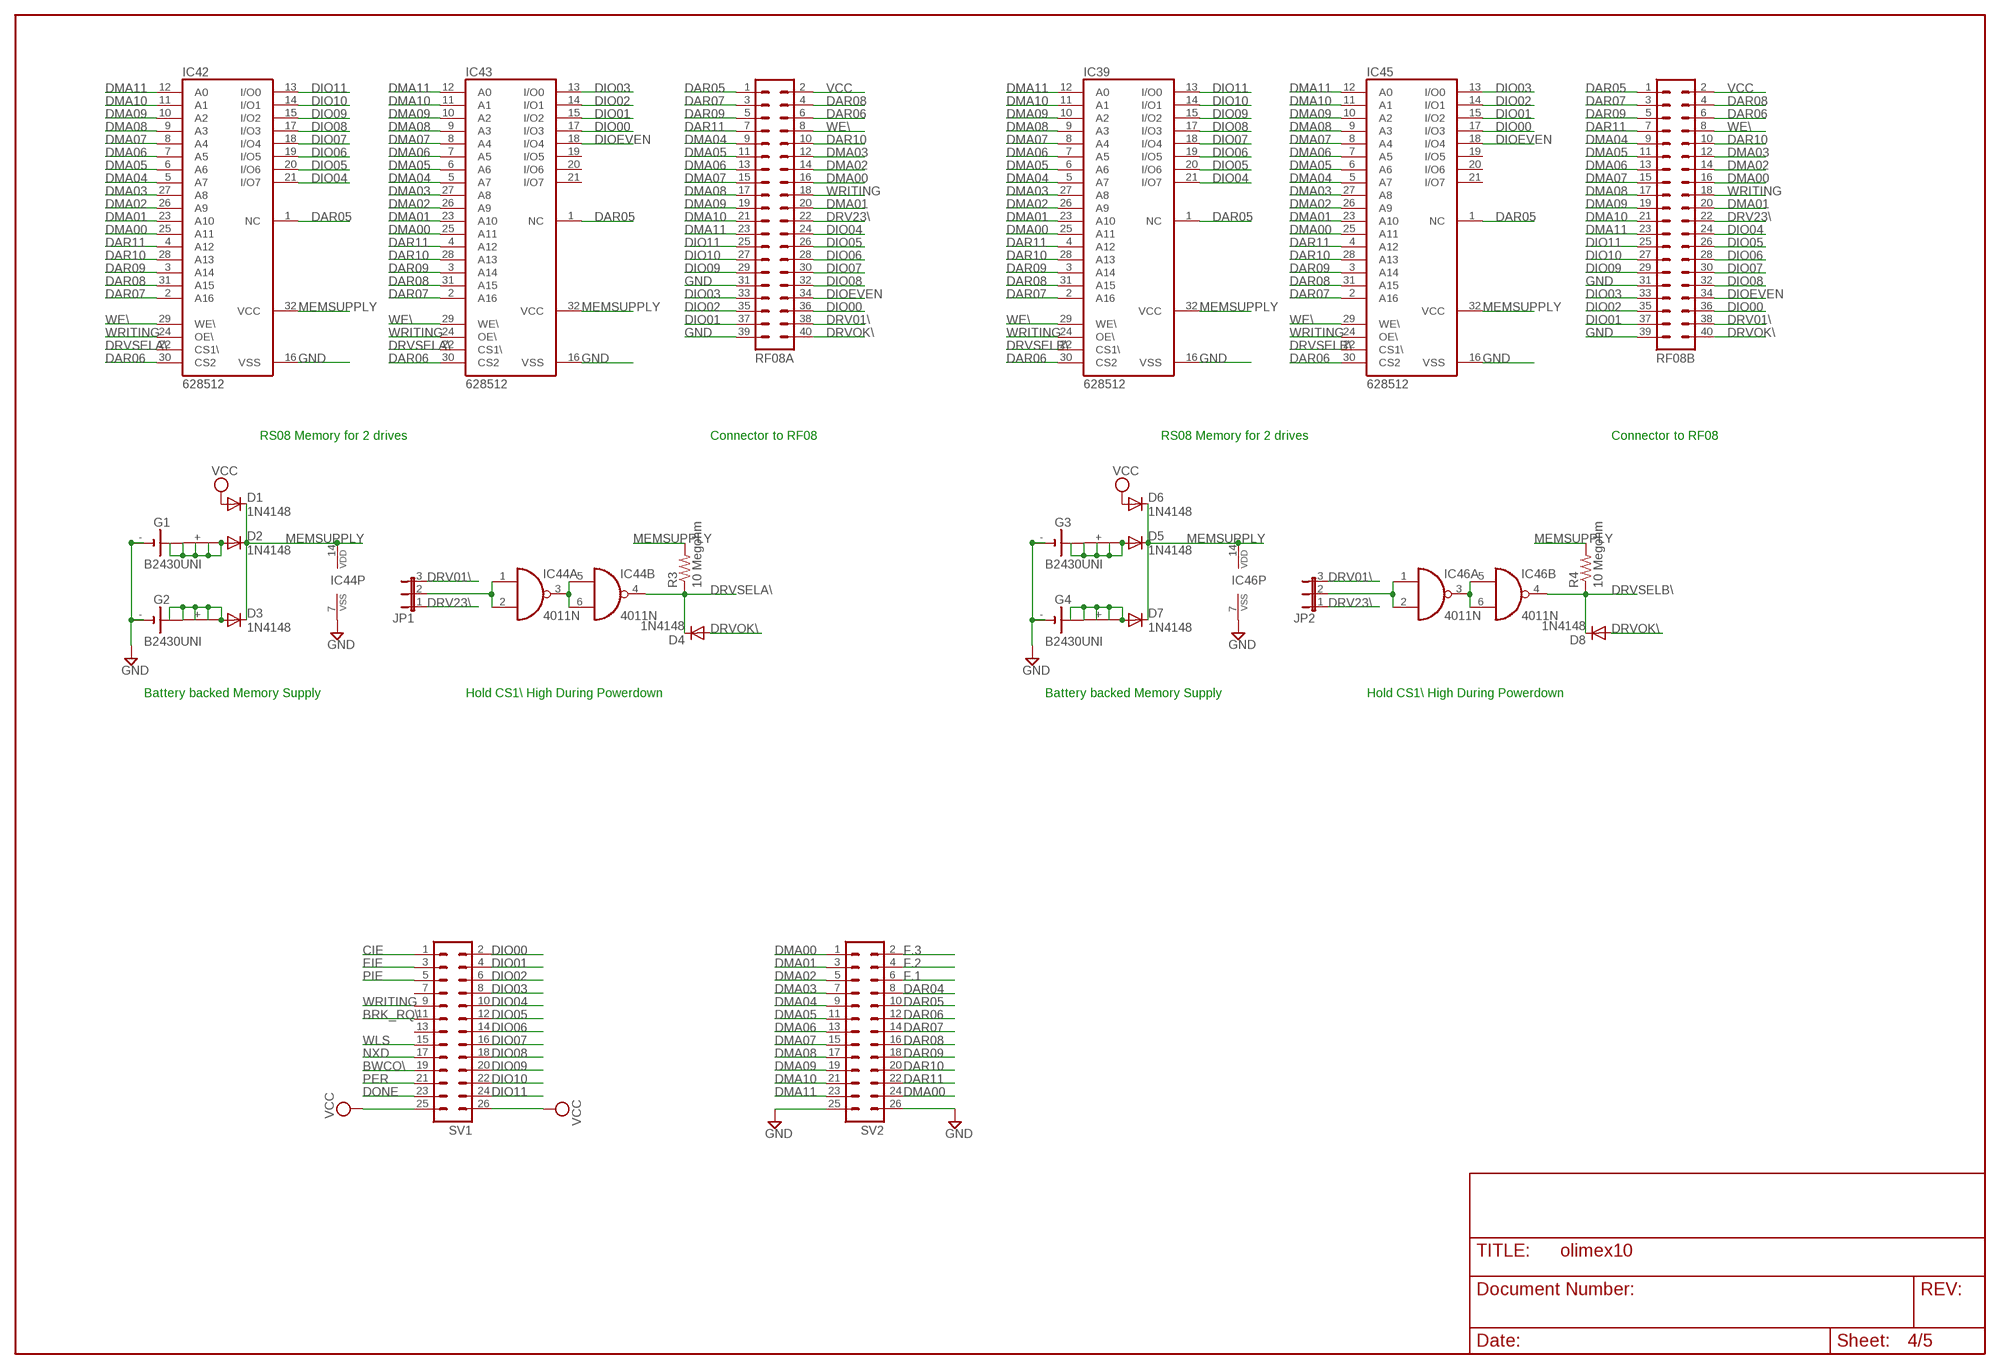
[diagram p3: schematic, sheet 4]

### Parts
D1  1N4148  [DO35-10]
D2  1N4148  [DO35-10]
D3  1N4148  [DO35-10]
D4  1N4148  [DO35-10]
D5  1N4148  [DO35-10]
D6  1N4148  [DO35-10]
D7  1N4148  [DO35-10]
D8  1N4148  [DO35-10]
G1  B2430UNI  [B2430UNI]
G2  B2430UNI  [B2430UNI]
G3  B2430UNI  [B2430UNI]
G4  B2430UNI  [B2430UNI]
IC39  628512  628128P  [DIL32]
IC42  628512  628128P  [DIL32]
IC43  628512  628128P  [DIL32]
IC44  4011N  [DIL14]
IC45  628512  628128P  [DIL32]
IC46  4011N  [DIL14]
JP1  JP2E  [JP2]
JP2  JP2E  [JP2]
R3  10 Megohm  R-US_0207/10  [0207/10]
R4  10 Megohm  R-US_0207/10  [0207/10]
RF08A  MA20-2  [MA20-2]
RF08B  MA20-2  [MA20-2]
SV1  MA13-2  [MA13-2]
SV2  MA13-2  [MA13-2]

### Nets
BRK_RQ\: SV1.11 ; also sheet 1,5
BWCO\: SV1.19 ; also sheet 1,5
CIE: SV1.1 ; also sheet 2,5
DAR04: SV2.8 ; also sheet 2,3,5
DAR05: IC39.1(NC) IC42.1(NC) IC43.1(NC) IC45.1(NC) RF08A.1 RF08B.1 SV2.10 ; also sheet 2,3,5
DAR06: IC39.30(CS2) IC42.30(CS2) IC43.30(CS2) IC45.30(CS2) RF08A.6 RF08B.6 SV2.12 ; also sheet 2,3,5
DAR07: IC39.2(A16) IC42.2(A16) IC43.2(A16) IC45.2(A16) RF08A.3 RF08B.3 SV2.14 ; also sheet 2,3,5
DAR08: IC39.31(A15) IC42.31(A15) IC43.31(A15) IC45.31(A15) RF08A.4 RF08B.4 SV2.16 ; also sheet 2,3,5
DAR09: IC39.3(A14) IC42.3(A14) IC43.3(A14) IC45.3(A14) RF08A.5 RF08B.5 SV2.18 ; also sheet 2,3,5
DAR10: IC39.28(A13) IC42.28(A13) IC43.28(A13) IC45.28(A13) RF08A.10 RF08B.10 SV2.20 ; also sheet 2,3,5
DAR11: IC39.4(A12) IC42.4(A12) IC43.4(A12) IC45.4(A12) RF08A.7 RF08B.7 SV2.22 ; also sheet 2,3,5
DIO00: IC43.17(I/O3) IC45.17(I/O3) RF08A.36 RF08B.36 SV1.2 ; also sheet 3,5
DIO01: IC43.15(I/O2) IC45.15(I/O2) RF08A.37 RF08B.37 SV1.4 ; also sheet 3,5
DIO02: IC43.14(I/O1) IC45.14(I/O1) RF08A.35 RF08B.35 SV1.6 ; also sheet 3,5
DIO03: IC43.13(I/O0) IC45.13(I/O0) RF08A.33 RF08B.33 SV1.8 ; also sheet 3,5
DIO04: IC39.21(I/O7) IC42.21(I/O7) RF08A.24 RF08B.24 SV1.10 ; also sheet 3,5
DIO05: IC39.20(I/O6) IC42.20(I/O6) RF08A.26 RF08B.26 SV1.12 ; also sheet 3,5
DIO06: IC39.19(I/O5) IC42.19(I/O5) RF08A.28 RF08B.28 SV1.14 ; also sheet 3,5
DIO07: IC39.18(I/O4) IC42.18(I/O4) RF08A.30 RF08B.30 SV1.16 ; also sheet 3,5
DIO08: IC39.17(I/O3) IC42.17(I/O3) RF08A.32 RF08B.32 SV1.18 ; also sheet 3,5
DIO09: IC39.15(I/O2) IC42.15(I/O2) RF08A.29 RF08B.29 SV1.20 ; also sheet 3,5
DIO10: IC39.14(I/O1) IC42.14(I/O1) RF08A.27 RF08B.27 SV1.22 ; also sheet 3,5
DIO11: IC39.13(I/O0) IC42.13(I/O0) RF08A.25 RF08B.25 SV1.24 ; also sheet 3,5
DIOEVEN: IC43.18(I/O4) IC45.18(I/O4) RF08A.34 RF08B.34 ; also sheet 3
DMA00: IC39.25(A11) IC42.25(A11) IC43.25(A11) IC45.25(A11) RF08A.16 RF08B.16 SV2.1 SV2.24 ; also sheet 2,3,5
DMA01: IC39.23(A10) IC42.23(A10) IC43.23(A10) IC45.23(A10) RF08A.20 RF08B.20 SV2.3 ; also sheet 2,3,5
DMA02: IC39.26(A9) IC42.26(A9) IC43.26(A9) IC45.26(A9) RF08A.14 RF08B.14 SV2.5 ; also sheet 2,3,5
DMA03: IC39.27(A8) IC42.27(A8) IC43.27(A8) IC45.27(A8) RF08A.12 RF08B.12 SV2.7 ; also sheet 2,3,5
DMA04: IC39.5(A7) IC42.5(A7) IC43.5(A7) IC45.5(A7) RF08A.9 RF08B.9 SV2.9 ; also sheet 2,3,5
DMA05: IC39.6(A6) IC42.6(A6) IC43.6(A6) IC45.6(A6) RF08A.11 RF08B.11 SV2.11 ; also sheet 2,3,5
DMA06: IC39.7(A5) IC42.7(A5) IC43.7(A5) IC45.7(A5) RF08A.13 RF08B.13 SV2.13 ; also sheet 2,3,5
DMA07: IC39.8(A4) IC42.8(A4) IC43.8(A4) IC45.8(A4) RF08A.15 RF08B.15 SV2.15 ; also sheet 2,3,5
DMA08: IC39.9(A3) IC42.9(A3) IC43.9(A3) IC45.9(A3) RF08A.17 RF08B.17 SV2.17 ; also sheet 2,3,5
DMA09: IC39.10(A2) IC42.10(A2) IC43.10(A2) IC45.10(A2) RF08A.19 RF08B.19 SV2.19 ; also sheet 2,3,5
DMA10: IC39.11(A1) IC42.11(A1) IC43.11(A1) IC45.11(A1) RF08A.21 RF08B.21 SV2.21 ; also sheet 2,3,5
DMA11: IC39.12(A0) IC42.12(A0) IC43.12(A0) IC45.12(A0) RF08A.23 RF08B.23 SV2.23 ; also sheet 2,3,5
DONE: SV1.23 ; also sheet 1,2,5
DRV01\: JP1.3 JP2.3 RF08A.38 RF08B.38 ; also sheet 3
DRV23\: JP1.1 JP2.1 RF08A.22 RF08B.22 ; also sheet 3
DRVOK\: D4.A D8.A RF08A.40 RF08B.40 ; also sheet 3
DRVSELA\: D4.C IC42.22(CS1\) IC43.22(CS1\) IC44.4(B:O) R3.1
DRVSELB\: D8.C IC39.22(CS1\) IC45.22(CS1\) IC46.4(B:O) R4.1
EIE: SV1.3 ; also sheet 2,5
F.1: SV2.6 ; also sheet 1,2,5
F.2: SV2.4 ; also sheet 1,2,5
F.3: SV2.2 ; also sheet 1,2,5
GND: G1.- G1.-@1(-) G2.- G2.-@1(-) G3.- G3.-@1(-) G4.- G4.-@1(-) IC39.16(VSS) IC42.16(VSS) IC43.16(VSS) IC44.7(P:VSS) IC45.16(VSS) IC46.7(P:VSS) RF08A.31 RF08A.39 RF08B.31 RF08B.39 SV2.25 SV2.26 ; also sheet 1,2,3,5
MEMSUPPLY [Power]: D1.C D2.C D3.C D5.C D6.C D7.C IC39.32(VCC) IC42.32(VCC) IC43.32(VCC) IC44.14(P:VDD) IC45.32(VCC) IC46.14(P:VDD) R3.2 R4.2
N$18: IC44.3(A:O) IC44.5(B:I0) IC44.6(B:I1)
N$35: IC44.1(A:I0) IC44.2(A:I1) JP1.2
N$36: D7.A G4.+ G4.+@1(+) G4.+@2(+) G4.+@3(+) G4.+@4(+)
N$38: IC46.3(A:O) IC46.5(B:I0) IC46.6(B:I1)
N$39: IC46.1(A:I0) IC46.2(A:I1) JP2.2
N$41: D5.A G3.+ G3.+@1(+) G3.+@2(+) G3.+@3(+) G3.+@4(+)
N$130: D3.A G2.+ G2.+@1(+) G2.+@2(+) G2.+@3(+) G2.+@4(+)
N$131: D2.A G1.+ G1.+@1(+) G1.+@2(+) G1.+@3(+) G1.+@4(+)
NXD: SV1.17 ; also sheet 2,5
PER: SV1.21 ; also sheet 2,5
PIE: SV1.5 ; also sheet 2,5
VCC [Power]: D1.A D6.A RF08A.2 RF08B.2 SV1.25 SV1.26 ; also sheet 1,2,3,5
WE\: IC39.29(WE\) IC42.29(WE\) IC43.29(WE\) IC45.29(WE\) RF08A.8 RF08B.8 ; also sheet 1,3
WLS: SV1.15 ; also sheet 2,5
WRITING: IC39.24(OE\) IC42.24(OE\) IC43.24(OE\) IC45.24(OE\) RF08A.18 RF08B.18 SV1.9 ; also sheet 1,3,5
Unconnected: IC43.19(I/O5) IC43.20(I/O6) IC43.21(I/O7) IC44.8(C:I0) IC44.9(C:I1) IC44.10(C:O) IC44.11(D:O) IC44.12(D:I0) IC44.13(D:I1) IC45.19(I/O5) IC45.20(I/O6) IC45.21(I/O7) IC46.8(C:I0) IC46.9(C:I1) IC46.10(C:O) IC46.11(D:O) IC46.12(D:I0) IC46.13(D:I1) SV1.7 SV1.13

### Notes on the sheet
- RS08 Memory for 2 drives | Connector to RF08 | RS08 Memory for 2 drives | Connector to RF08
- Battery backed Memory Supply | Hold CS1\ High During Powerdown | Battery backed Memory Supply | Hold CS1\ High During Powerdown

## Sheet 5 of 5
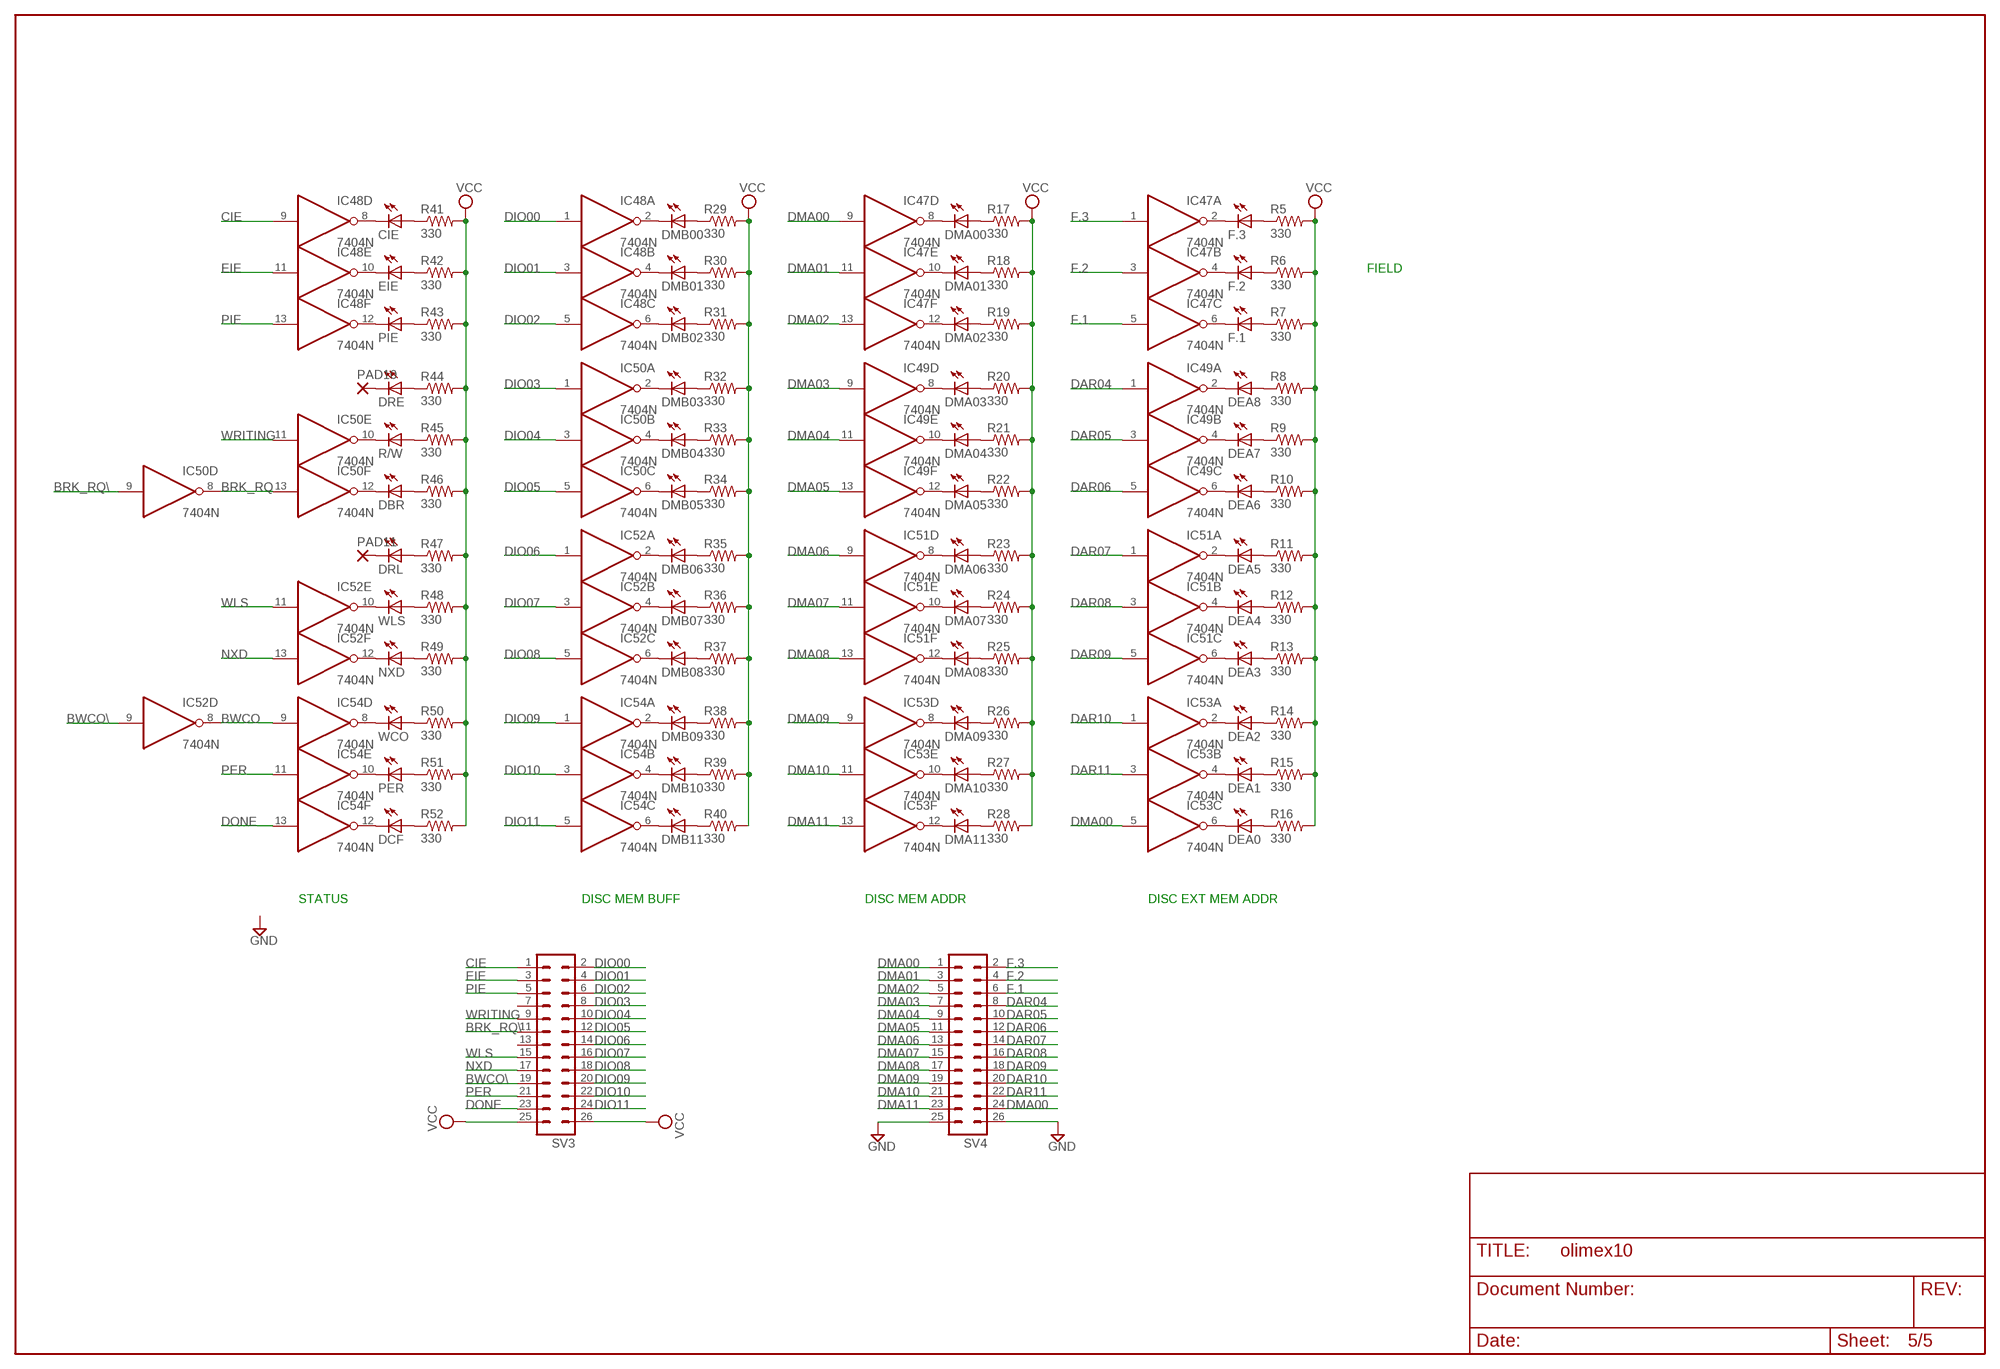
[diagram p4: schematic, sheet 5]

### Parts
CIE  LED5MM  [LED5MM]
DBR  LED5MM  [LED5MM]
DCF  LED5MM  [LED5MM]
DEA0  LED5MM  [LED5MM]
DEA1  LED5MM  [LED5MM]
DEA2  LED5MM  [LED5MM]
DEA3  LED5MM  [LED5MM]
DEA4  LED5MM  [LED5MM]
DEA5  LED5MM  [LED5MM]
DEA6  LED5MM  [LED5MM]
DEA7  LED5MM  [LED5MM]
DEA8  LED5MM  [LED5MM]
DMA00  LED5MM  [LED5MM]
DMA01  LED5MM  [LED5MM]
DMA02  LED5MM  [LED5MM]
DMA03  LED5MM  [LED5MM]
DMA04  LED5MM  [LED5MM]
DMA05  LED5MM  [LED5MM]
DMA06  LED5MM  [LED5MM]
DMA07  LED5MM  [LED5MM]
DMA08  LED5MM  [LED5MM]
DMA09  LED5MM  [LED5MM]
DMA10  LED5MM  [LED5MM]
DMA11  LED5MM  [LED5MM]
DMB00  LED5MM  [LED5MM]
DMB01  LED5MM  [LED5MM]
DMB02  LED5MM  [LED5MM]
DMB03  LED5MM  [LED5MM]
DMB04  LED5MM  [LED5MM]
DMB05  LED5MM  [LED5MM]
DMB06  LED5MM  [LED5MM]
DMB07  LED5MM  [LED5MM]
DMB08  LED5MM  [LED5MM]
DMB09  LED5MM  [LED5MM]
DMB10  LED5MM  [LED5MM]
DMB11  LED5MM  [LED5MM]
DRE  LED5MM  [LED5MM]
DRL  LED5MM  [LED5MM]
EIE  LED5MM  [LED5MM]
F.1  LED5MM  [LED5MM]
F.2  LED5MM  [LED5MM]
F.3  LED5MM  [LED5MM]
IC47  7404N  [DIL14]
IC48  7404N  [DIL14]
IC49  7404N  [DIL14]
IC50  7404N  [DIL14]
IC51  7404N  [DIL14]
IC52  7404N  [DIL14]
IC53  7404N  [DIL14]
IC54  7404N  [DIL14]
NXD  LED5MM  [LED5MM]
PAD10  1,6/0,8  [1,6/0,8]
PAD11  1,6/0,8  [1,6/0,8]
PER  LED5MM  [LED5MM]
PIE  LED5MM  [LED5MM]
R5  330  R-US_0207/10  [0207/10]
R6  330  R-US_0207/10  [0207/10]
R7  330  R-US_0207/10  [0207/10]
R8  330  R-US_0207/10  [0207/10]
R9  330  R-US_0207/10  [0207/10]
R10  330  R-US_0207/10  [0207/10]
R11  330  R-US_0207/10  [0207/10]
R12  330  R-US_0207/10  [0207/10]
R13  330  R-US_0207/10  [0207/10]
R14  330  R-US_0207/10  [0207/10]
R15  330  R-US_0207/10  [0207/10]
R16  330  R-US_0207/10  [0207/10]
R17  330  R-US_0207/10  [0207/10]
R18  330  R-US_0207/10  [0207/10]
R19  330  R-US_0207/10  [0207/10]
R20  330  R-US_0207/10  [0207/10]
R21  330  R-US_0207/10  [0207/10]
R22  330  R-US_0207/10  [0207/10]
R23  330  R-US_0207/10  [0207/10]
R24  330  R-US_0207/10  [0207/10]
R25  330  R-US_0207/10  [0207/10]
R26  330  R-US_0207/10  [0207/10]
R27  330  R-US_0207/10  [0207/10]
R28  330  R-US_0207/10  [0207/10]
R29  330  R-US_0207/10  [0207/10]
R30  330  R-US_0207/10  [0207/10]
R31  330  R-US_0207/10  [0207/10]
R32  330  R-US_0207/10  [0207/10]
R33  330  R-US_0207/10  [0207/10]
R34  330  R-US_0207/10  [0207/10]
R35  330  R-US_0207/10  [0207/10]
R36  330  R-US_0207/10  [0207/10]
R37  330  R-US_0207/10  [0207/10]
R38  330  R-US_0207/10  [0207/10]
R39  330  R-US_0207/10  [0207/10]
R40  330  R-US_0207/10  [0207/10]
R41  330  R-US_0207/10  [0207/10]
R42  330  R-US_0207/10  [0207/10]
R43  330  R-US_0207/10  [0207/10]
R44  330  R-US_0207/10  [0207/10]
R45  330  R-US_0207/10  [0207/10]
R46  330  R-US_0207/10  [0207/10]
R47  330  R-US_0207/10  [0207/10]
R48  330  R-US_0207/10  [0207/10]
R49  330  R-US_0207/10  [0207/10]
R50  330  R-US_0207/10  [0207/10]
R51  330  R-US_0207/10  [0207/10]
R52  330  R-US_0207/10  [0207/10]
R/W  LED5MM  [LED5MM]
SV3  MA13-2  [MA13-2]
SV4  MA13-2  [MA13-2]
WCO  LED5MM  [LED5MM]
WLS  LED5MM  [LED5MM]

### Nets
BRK_RQ: IC50.8(D:O) IC50.13(F:I)
BRK_RQ\: IC50.9(D:I) SV3.11 ; also sheet 1,4
BWCO: IC52.8(D:O) IC54.9(D:I)
BWCO\: IC52.9(D:I) SV3.19 ; also sheet 1,4
CIE: IC48.9(D:I) SV3.1 ; also sheet 2,4
DAR04: IC49.1(A:I) SV4.8 ; also sheet 2,3,4
DAR05: IC49.3(B:I) SV4.10 ; also sheet 2,3,4
DAR06: IC49.5(C:I) SV4.12 ; also sheet 2,3,4
DAR07: IC51.1(A:I) SV4.14 ; also sheet 2,3,4
DAR08: IC51.3(B:I) SV4.16 ; also sheet 2,3,4
DAR09: IC51.5(C:I) SV4.18 ; also sheet 2,3,4
DAR10: IC53.1(A:I) SV4.20 ; also sheet 2,3,4
DAR11: IC53.3(B:I) SV4.22 ; also sheet 2,3,4
DIO00: IC48.1(A:I) SV3.2 ; also sheet 3,4
DIO01: IC48.3(B:I) SV3.4 ; also sheet 3,4
DIO02: IC48.5(C:I) SV3.6 ; also sheet 3,4
DIO03: IC50.1(A:I) SV3.8 ; also sheet 3,4
DIO04: IC50.3(B:I) SV3.10 ; also sheet 3,4
DIO05: IC50.5(C:I) SV3.12 ; also sheet 3,4
DIO06: IC52.1(A:I) SV3.14 ; also sheet 3,4
DIO07: IC52.3(B:I) SV3.16 ; also sheet 3,4
DIO08: IC52.5(C:I) SV3.18 ; also sheet 3,4
DIO09: IC54.1(A:I) SV3.20 ; also sheet 3,4
DIO10: IC54.3(B:I) SV3.22 ; also sheet 3,4
DIO11: IC54.5(C:I) SV3.24 ; also sheet 3,4
DMA00: IC47.9(D:I) IC53.5(C:I) SV4.1 SV4.24 ; also sheet 2,3,4
DMA01: IC47.11(E:I) SV4.3 ; also sheet 2,3,4
DMA02: IC47.13(F:I) SV4.5 ; also sheet 2,3,4
DMA03: IC49.9(D:I) SV4.7 ; also sheet 2,3,4
DMA04: IC49.11(E:I) SV4.9 ; also sheet 2,3,4
DMA05: IC49.13(F:I) SV4.11 ; also sheet 2,3,4
DMA06: IC51.9(D:I) SV4.13 ; also sheet 2,3,4
DMA07: IC51.11(E:I) SV4.15 ; also sheet 2,3,4
DMA08: IC51.13(F:I) SV4.17 ; also sheet 2,3,4
DMA09: IC53.9(D:I) SV4.19 ; also sheet 2,3,4
DMA10: IC53.11(E:I) SV4.21 ; also sheet 2,3,4
DMA11: IC53.13(F:I) SV4.23 ; also sheet 2,3,4
DONE: IC54.13(F:I) SV3.23 ; also sheet 1,2,4
EIE: IC48.11(E:I) SV3.3 ; also sheet 2,4
F.1: IC47.5(C:I) SV4.6 ; also sheet 1,2,4
F.2: IC47.3(B:I) SV4.4 ; also sheet 1,2,4
F.3: IC47.1(A:I) SV4.2 ; also sheet 1,2,4
GND: SV4.25 SV4.26 ; also sheet 1,2,3,4
N$42: F.3.A R5.1
N$43: F.2.A R6.1
N$44: F.1.A R7.1
N$45: DEA8.A R8.1
N$46: DEA7.A R9.1
N$47: DEA6.A R10.1
N$48: DEA5.A R11.1
N$49: DEA4.A R12.1
N$50: DEA3.A R13.1
N$51: DEA2.A R14.1
N$52: DEA1.A R15.1
N$85: DEA0.A R16.1
N$86: DMA00.A R17.1
N$87: DMA01.A R18.1
N$88: DMA02.A R19.1
N$89: DMA03.A R20.1
N$90: DMA04.A R21.1
N$91: DMA05.A R22.1
N$92: DMA06.A R23.1
N$93: DMA07.A R24.1
N$94: DMA08.A R25.1
N$95: DMA09.A R26.1
N$96: DMA10.A R27.1
N$97: DMA11.A R28.1
N$98: DMB00.A R29.1
N$99: DMB01.A R30.1
N$100: DMB02.A R31.1
N$101: DMB03.A R32.1
N$102: DMB04.A R33.1
N$103: DMB05.A R34.1
N$104: DMB06.A R35.1
N$105: DMB07.A R36.1
N$106: DMB08.A R37.1
N$107: DMB09.A R38.1
N$108: DMB10.A R39.1
N$109: DMB11.A R40.1
N$110: CIE.A R41.1
N$111: EIE.A R42.1
N$112: PIE.A R43.1
N$113: DRE.A R44.1
N$114: R45.1 R/W.A
N$115: DBR.A R46.1
N$116: DRL.A R47.1
N$117: R48.1 WLS.A
N$118: NXD.A R49.1
N$119: R50.1 WCO.A
N$120: PER.A R51.1
N$121: DCF.A R52.1
N$122: F.3.K(C) IC47.2(A:O)
N$123: F.2.K(C) IC47.4(B:O)
N$124: F.1.K(C) IC47.6(C:O)
N$125: DMA00.K(C) IC47.8(D:O)
N$126: DMA01.K(C) IC47.10(E:O)
N$127: DMA02.K(C) IC47.12(F:O)
N$128: DMB00.K(C) IC48.2(A:O)
N$129: DMB01.K(C) IC48.4(B:O)
N$132: DMB02.K(C) IC48.6(C:O)
N$133: CIE.K(C) IC48.8(D:O)
N$134: EIE.K(C) IC48.10(E:O)
N$135: IC48.12(F:O) PIE.K(C)
N$136: DEA7.K(C) IC49.4(B:O)
N$137: DEA6.K(C) IC49.6(C:O)
N$138: DMA03.K(C) IC49.8(D:O)
N$139: DMA04.K(C) IC49.10(E:O)
N$140: DMA05.K(C) IC49.12(F:O)
N$141: DMB03.K(C) IC50.2(A:O)
N$142: DMB04.K(C) IC50.4(B:O)
N$143: DMB05.K(C) IC50.6(C:O)
N$144: IC50.10(E:O) R/W.K(C)
N$145: DBR.K(C) IC50.12(F:O)
N$146: DEA5.K(C) IC51.2(A:O)
N$147: DEA4.K(C) IC51.4(B:O)
N$148: DEA3.K(C) IC51.6(C:O)
N$149: DMA06.K(C) IC51.8(D:O)
N$150: DMA07.K(C) IC51.10(E:O)
N$151: DMA08.K(C) IC51.12(F:O)
N$152: DMB06.K(C) IC52.2(A:O)
N$153: DMB07.K(C) IC52.4(B:O)
N$154: DMB08.K(C) IC52.6(C:O)
N$155: IC52.10(E:O) WLS.K(C)
N$156: IC52.12(F:O) NXD.K(C)
N$157: DEA2.K(C) IC53.2(A:O)
N$158: DEA1.K(C) IC53.4(B:O)
N$159: DEA0.K(C) IC53.6(C:O)
N$160: DMA09.K(C) IC53.8(D:O)
N$161: DMA10.K(C) IC53.10(E:O)
N$162: DMA11.K(C) IC53.12(F:O)
N$163: DMB09.K(C) IC54.2(A:O)
N$164: DMB10.K(C) IC54.4(B:O)
N$165: DMB11.K(C) IC54.6(C:O)
N$166: IC54.8(D:O) WCO.K(C)
N$167: IC54.10(E:O) PER.K(C)
N$168: DCF.K(C) IC54.12(F:O)
N$169: DRE.K(C) PAD10.1(P)
N$170: DRL.K(C) PAD11.1(P)
N$171: DEA8.K(C) IC49.2(A:O)
NXD: IC52.13(F:I) SV3.17 ; also sheet 2,4
PER: IC54.11(E:I) SV3.21 ; also sheet 2,4
PIE: IC48.13(F:I) SV3.5 ; also sheet 2,4
VCC [Power]: R5.2 R6.2 R7.2 R8.2 R9.2 R10.2 R11.2 R12.2 R13.2 R14.2 R15.2 R16.2 R17.2 R18.2 R19.2 R20.2 R21.2 R22.2 R23.2 R24.2 R25.2 R26.2 R27.2 R28.2 R29.2 R30.2 R31.2 R32.2 R33.2 R34.2 R35.2 R36.2 R37.2 R38.2 R39.2 R40.2 R41.2 R42.2 R43.2 R44.2 R45.2 R46.2 R47.2 R48.2 R49.2 R50.2 R51.2 R52.2 SV3.25 SV3.26 ; also sheet 1,2,3,4
WLS: IC52.11(E:I) SV3.15 ; also sheet 2,4
WRITING: IC50.11(E:I) SV3.9 ; also sheet 1,3,4
Unconnected: SV3.7 SV3.13

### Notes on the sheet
- FIELD
- STATUS | DISC MEM BUFF | DISC MEM ADDR | DISC EXT MEM ADDR

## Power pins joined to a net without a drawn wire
GND: DAR4-7.8(GND) DAR8-11.8(GND) DMA0-3.8(GND) DMA4-7.8(GND) DMA8-11.8(GND) FIELD.8(GND) IC1.8(GND) IC2.8(GND) IC3.8(GND) IC4.8(GND) IC5.7(P:GND) IC6.8(P:GND) IC7.8(P:GND) IC9.7(P:GND) IC10.7(P:GND) IC11.7(P:GND) IC12.7(P:GND) IC13.7(GND) IC14.7(GND) IC15.7(GND) IC16.8(P:GND) IC17.8(P:GND) IC18.7(P:GND) IC19.7(P:GND) IC20.10(P:GND) IC21.8(P:GND) IC22.7(P:GND) IC23.7(P:GND) IC24.10(P:GND) IC25.8(GND) IC26.10(P:GND) IC28.10(P:GND) IC29.8(GND) IC30.10(P:GND) IC31.10(P:GND) IC32.8(GND) IC33.8(P:GND) IC34.10(P:GND) IC35.10(P:GND) IC36.8(GND) IC37.10(P:GND) IC38.10(P:GND) IC41.8(P:GND) IC47.7(P:GND) IC48.7(P:GND) IC49.7(P:GND) IC50.7(P:GND) IC51.7(P:GND) IC52.7(P:GND) IC53.7(P:GND) IC54.7(P:GND) IC55.7(P:GND) INTENB.8(GND)
VCC: DAR4-7.16(VCC) DAR8-11.16(VCC) DMA0-3.16(VCC) DMA4-7.16(VCC) DMA8-11.16(VCC) FIELD.16(VCC) IC1.16(VCC) IC2.16(VCC) IC3.16(VCC) IC4.16(VCC) IC5.14(P:VCC) IC6.16(P:VCC) IC7.16(P:VCC) IC9.14(P:VCC) IC10.14(P:VCC) IC11.14(P:VCC) IC12.14(P:VCC) IC13.14(VCC) IC14.14(VCC) IC15.14(VCC) IC16.16(P:VCC) IC17.16(P:VCC) IC18.14(P:VCC) IC19.14(P:VCC) IC20.20(P:VCC) IC21.16(P:VCC) IC22.14(P:VCC) IC23.14(P:VCC) IC24.20(P:VCC) IC25.16(VCC) IC26.20(P:VCC) IC28.20(P:VCC) IC29.16(VCC) IC30.20(P:VCC) IC31.20(P:VCC) IC32.16(VCC) IC33.16(P:VCC) IC34.20(P:VCC) IC35.20(P:VCC) IC36.16(VCC) IC37.20(P:VCC) IC38.20(P:VCC) IC41.16(P:VCC) IC47.14(P:VCC) IC48.14(P:VCC) IC49.14(P:VCC) IC50.14(P:VCC) IC51.14(P:VCC) IC52.14(P:VCC) IC53.14(P:VCC) IC54.14(P:VCC) IC55.14(P:VCC) INTENB.16(VCC)

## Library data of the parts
C1-C44 C46-C48 = rcl:C-US: CAPACITOR, American symbol
C35L C36L D34L D35L D36L RF08A RF08B RS08 = con-lstb:MA20-2: PIN HEADER
C45 = rcl:CPOL-US: POLARIZED CAPACITOR, American symbol
CIE DBR DCF DEA0 DEA1-DEA8 DMA00 DMA01-DMA09 DMA10 DMA11 DMB00 DMB01-DMB09 DMB10 DMB11 DRE DRL EIE F.1-F.3 NXD PER PIE R/W WCO WLS = led:LED: LED
D1-D8 = diode:1N4148: DIODE
DAR4-7 DAR8-11 DMA0-3 DMA4-7 DMA8-11 FIELD INTENB = 74xx-us:74*192: Synchronous 4-bit UP/DOWN COUNTER
G1-G4 = battery:B2430UNI: LI BATTERY
IC1-IC4 = 74xx-eu:74*151: Data SELECTOR/MULTIPLEXER
IC5 = 74xx-us:74*20: Dual 4-input NAND gate
IC6 IC7 IC16 IC17 IC21 IC33 IC41 = 74xx-us:74*139: Dual 2-line to 4-line DECODER/DEMULTIPLEXER
IC8 = linear:*555: TIMER
IC9-IC11 IC23 = 74xx-us:74*74: Dual D type positive edge triggered FLIP FLOP, preset and clear
IC12 IC18 = 74xx-eu:74*00: Quad 2-input NAND gate
IC13-IC15 = 74xx-us:74*180: 9-bit odd/even PARITY GENERATOR/CHECKER
IC19 IC22 = 74xx-us:74*07: Hex BUFFER, open collector high-voltage output
IC20 IC24 IC26 IC30 IC31 IC34 IC37 IC38 = 74xx-us:74*240: Octal BUFFER and LINE DRIVER, 3-state
IC25 IC29 IC32 IC36 = 74xx-us:74*138: 3-line to 8-line DECODER/DEMULTIPLEXER
IC27 = ic-package:DIL20: Dual In Line
IC28 IC35 = 74xx-us:74*244: Octal BUFFER and LINE DRIVER, 3-state
IC39 IC42 IC43 IC45 = memory-hitachi:628128P: MEMORY
IC44 IC46 = 40xx:4011: Quad 2-input NAND
IC47-IC54 = 74xx-us:74*04: Hex INVERTER
IC55 = 74xx-jameco:74*38: Quad 2-input NAND gate, open collector output
J2-J14 = jumper:J: Bridge
JP1 JP2 = jumper:JP2E: JUMPER
PAD1-PAD11 = wirepad:1,6/0,8: THROUGH-HOLE PAD
R1-R52 RA RB RL = rcl:R-US_: RESISTOR, American symbol
SV1-SV4 = con-lstb:MA13-2: PIN HEADER
SW1-SW4 = special:SW_DIP-8: DIP SWITCH

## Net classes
1 Power: width 0.508 mm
